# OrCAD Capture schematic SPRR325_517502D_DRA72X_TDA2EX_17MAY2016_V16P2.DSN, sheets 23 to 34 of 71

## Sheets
23 SH27 - DDR TERMNATION BANK 1: size B; rev: C
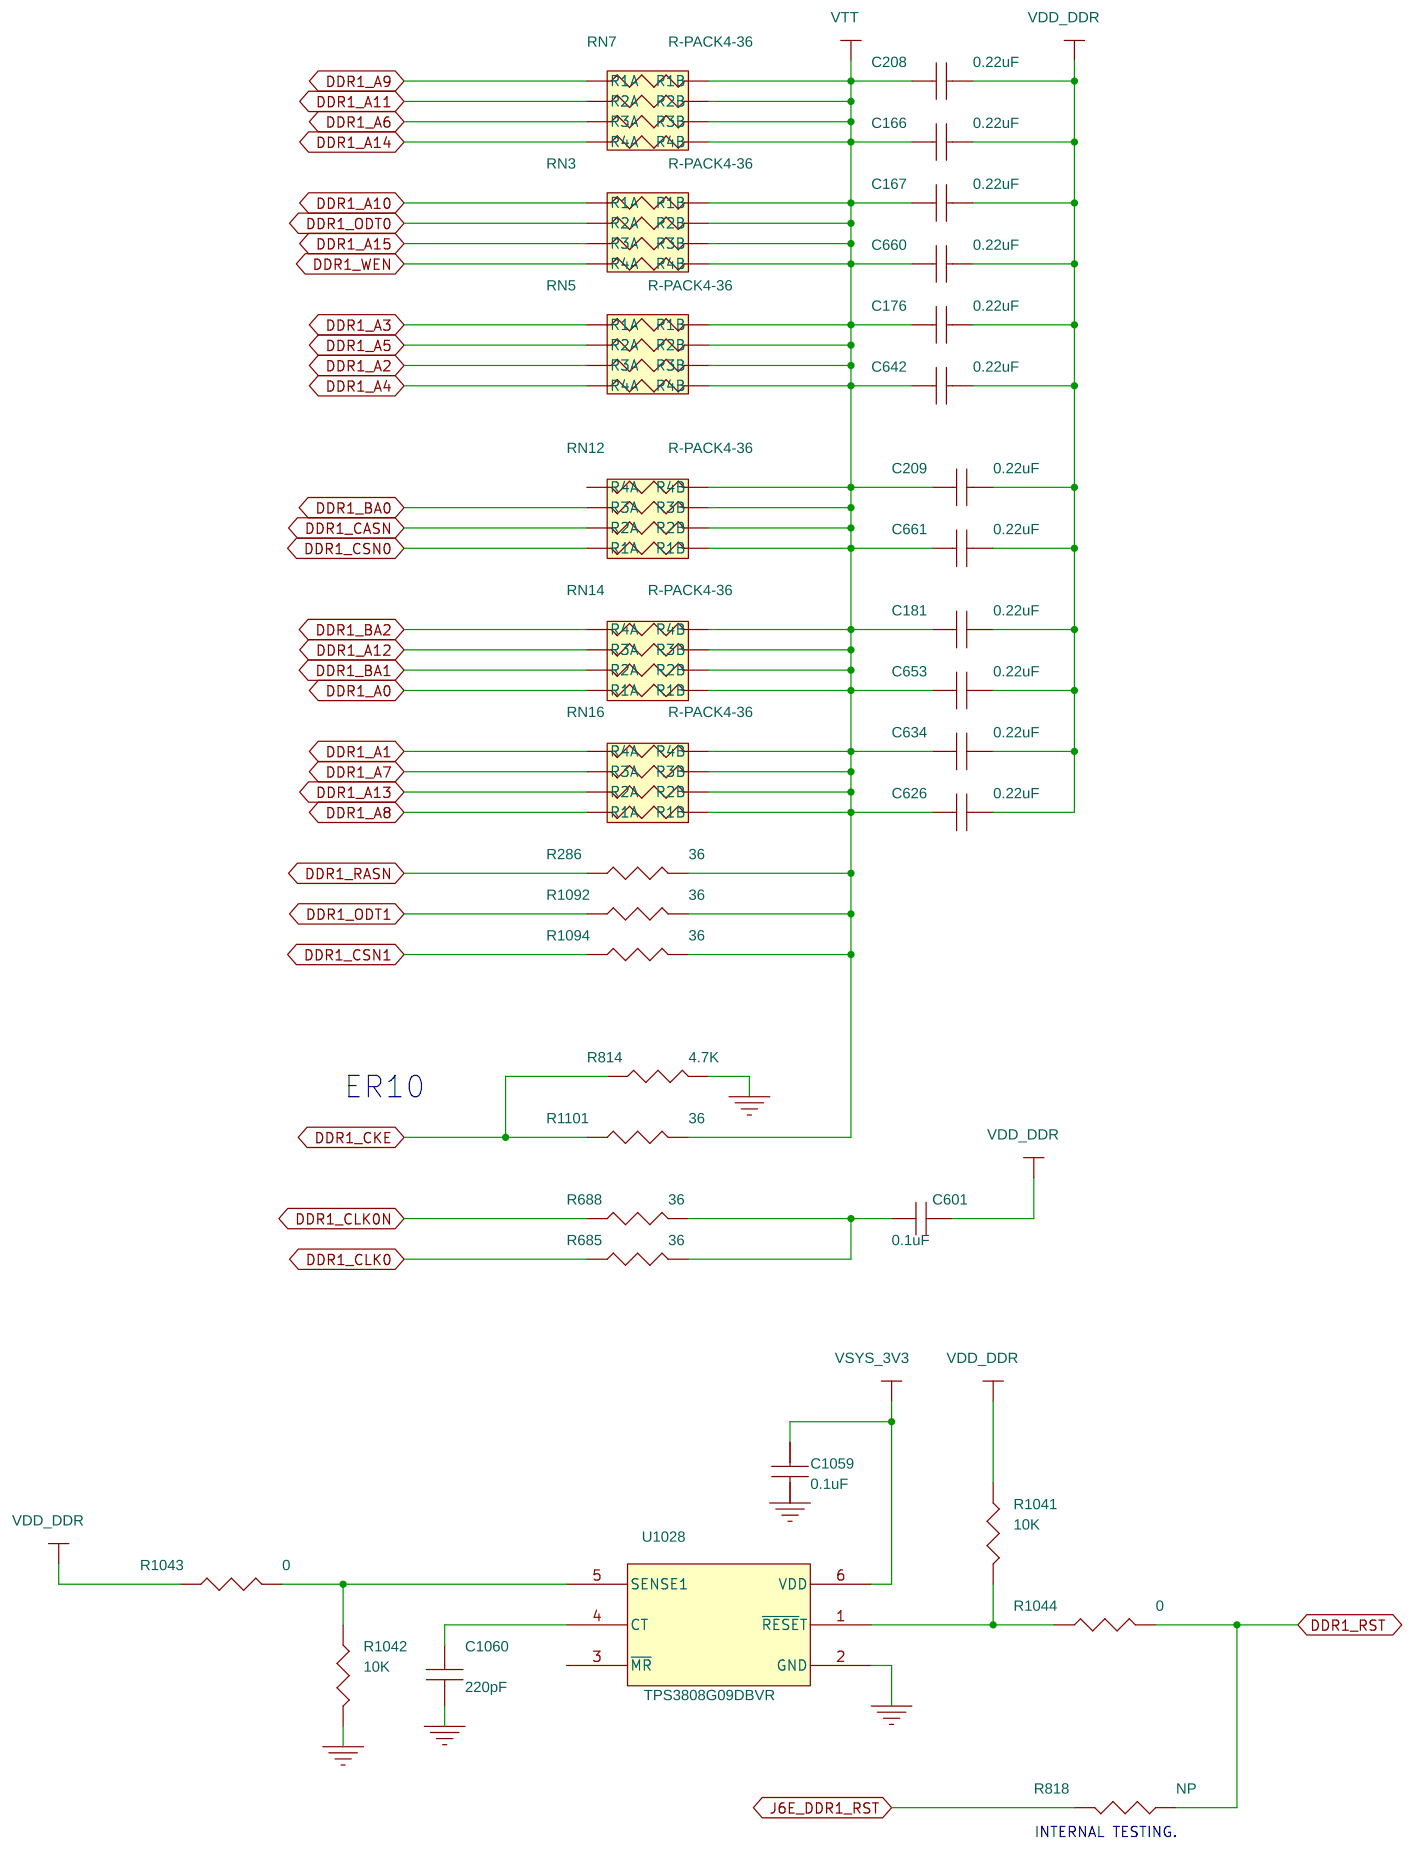
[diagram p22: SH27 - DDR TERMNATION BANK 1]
24 SH31 - MUX D GMPCA: size B; rev: A
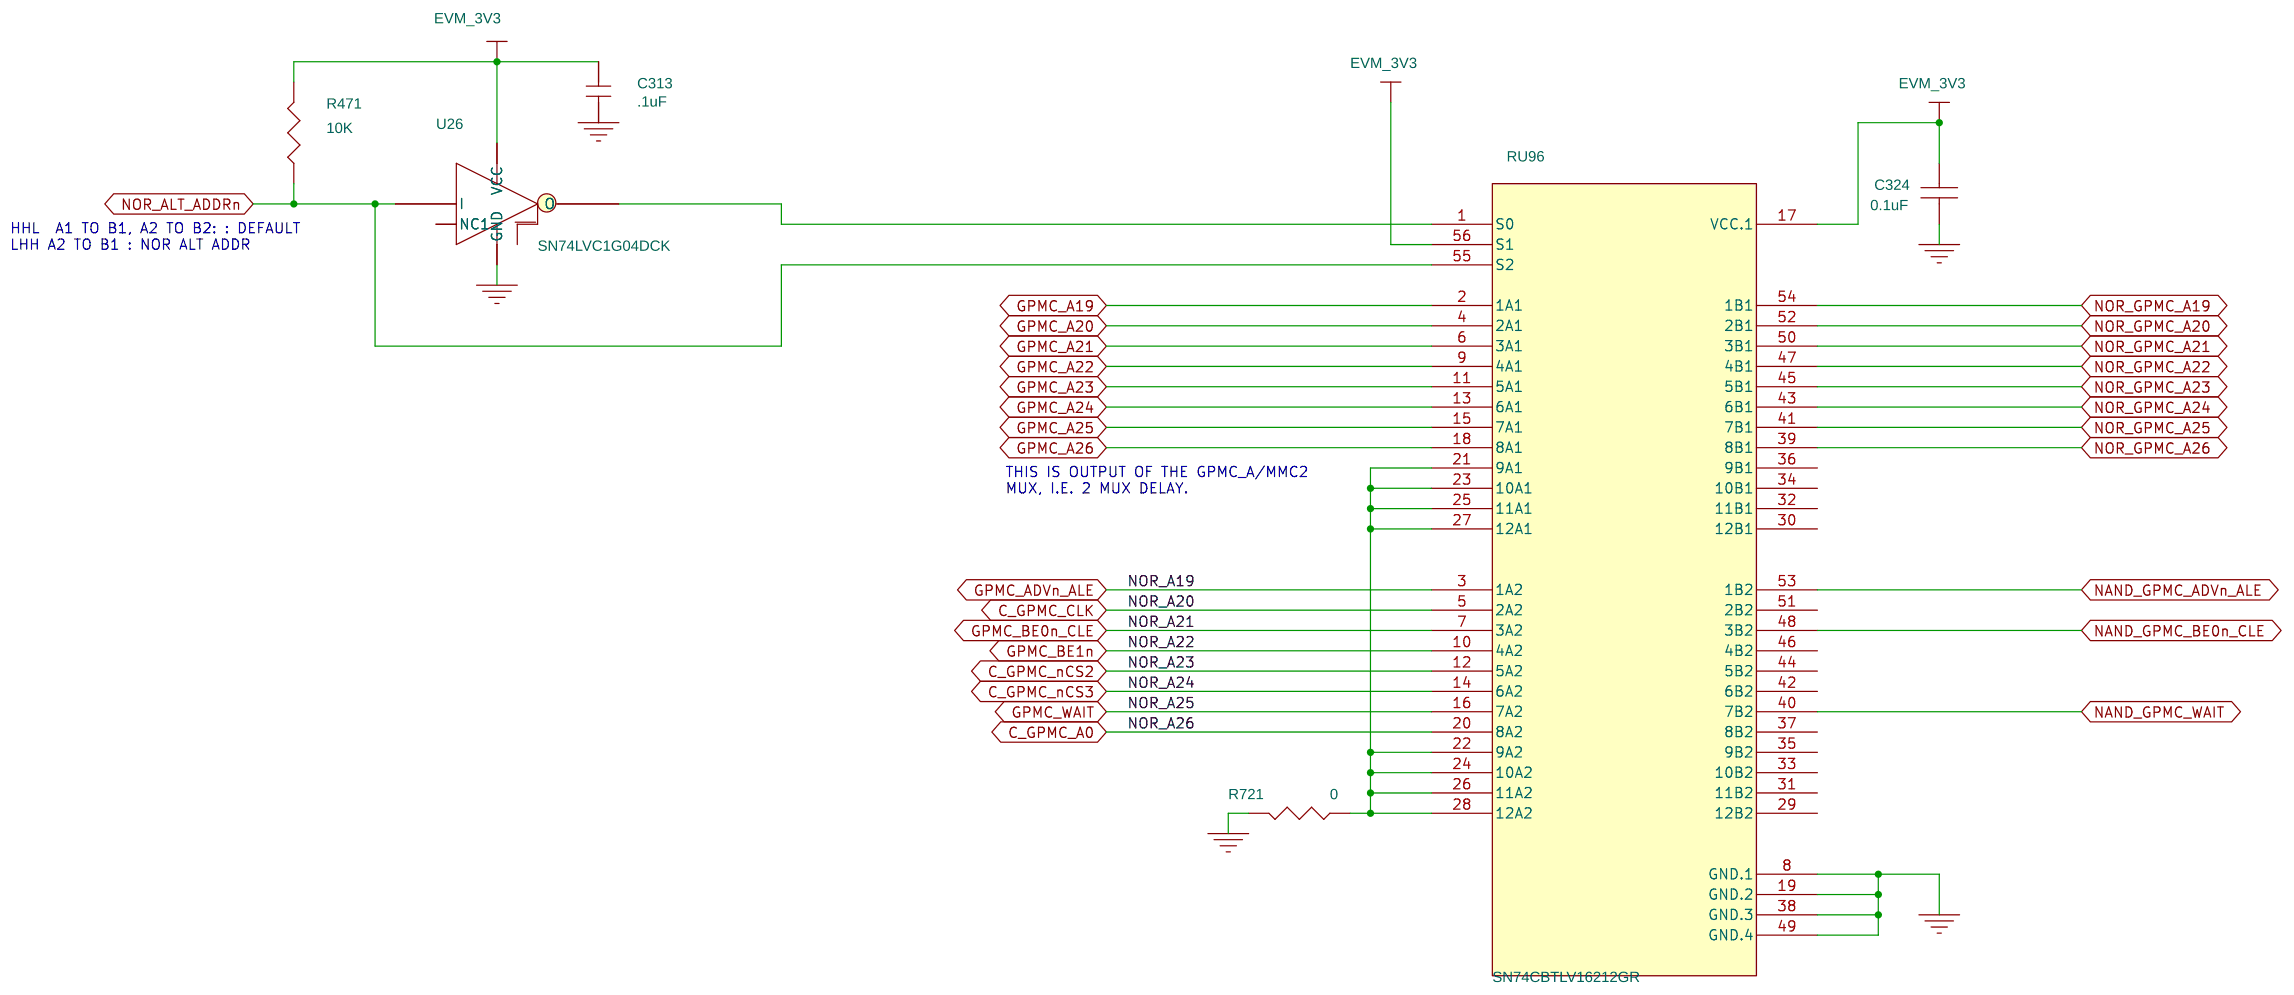
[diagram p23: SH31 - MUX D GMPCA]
25 SH32 - MUX E VIN2: size B
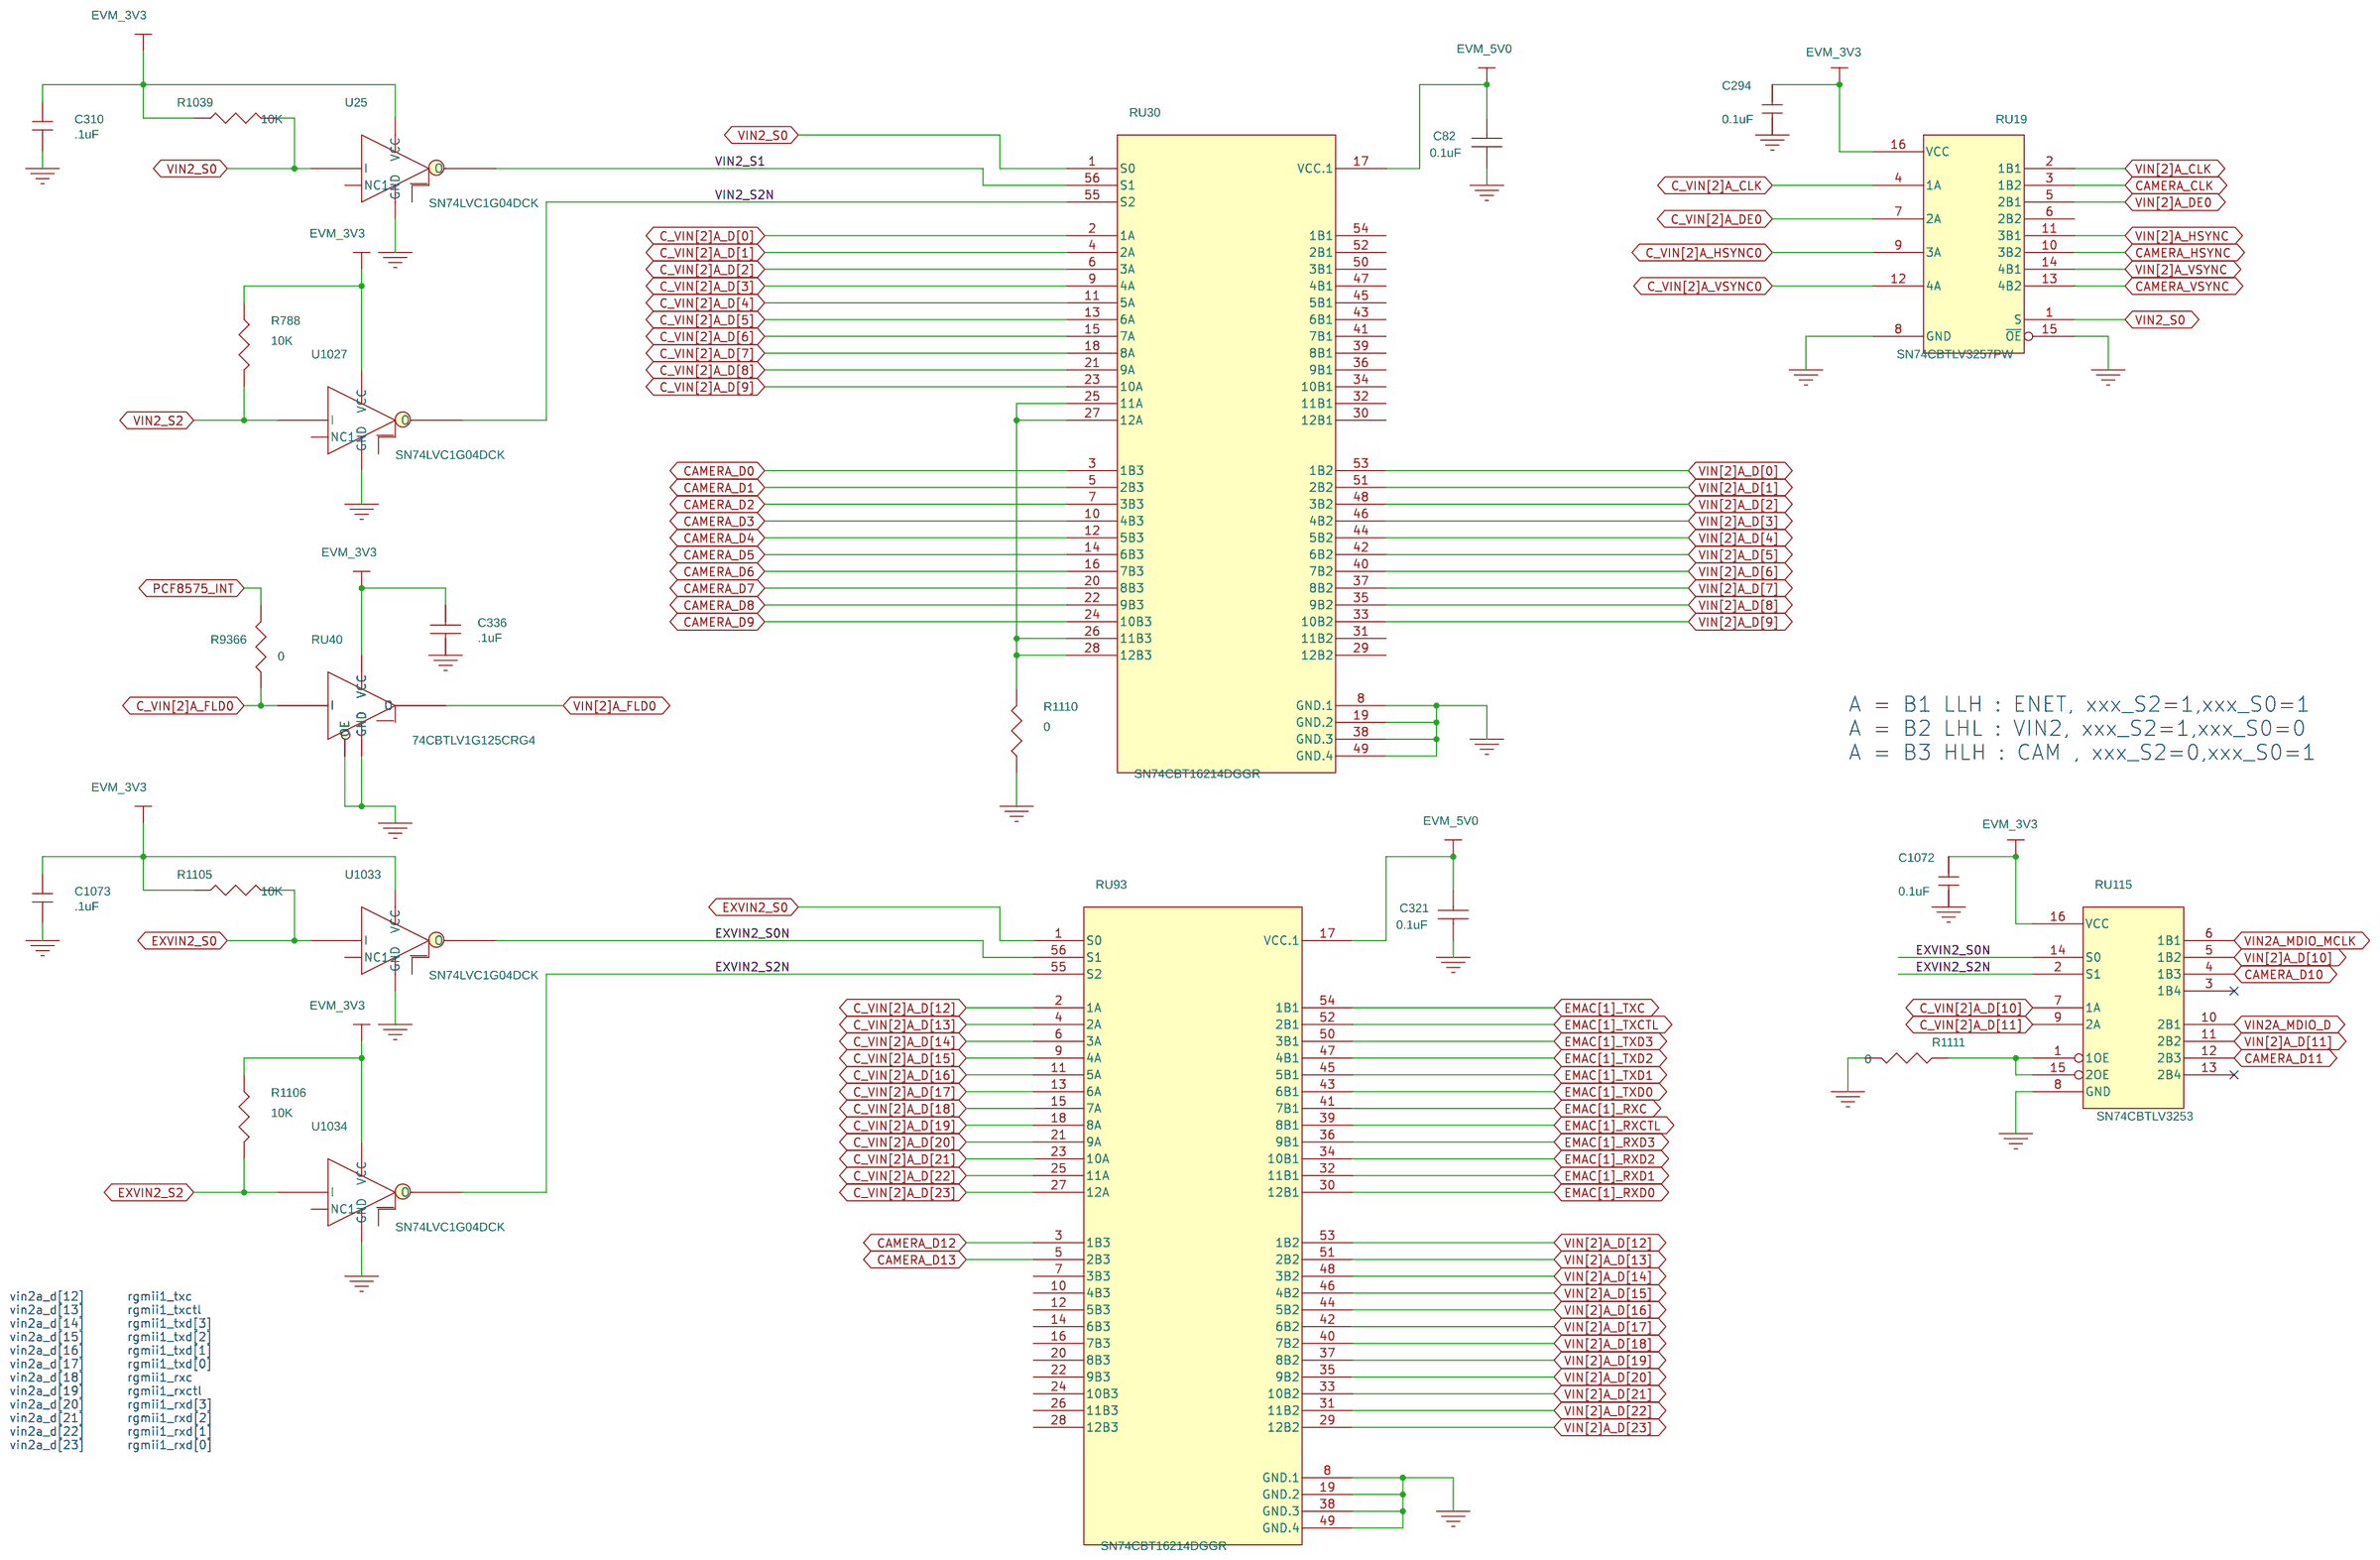
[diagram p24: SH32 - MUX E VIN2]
26 SH36 - MEM SPI FLASH: size B; rev: A
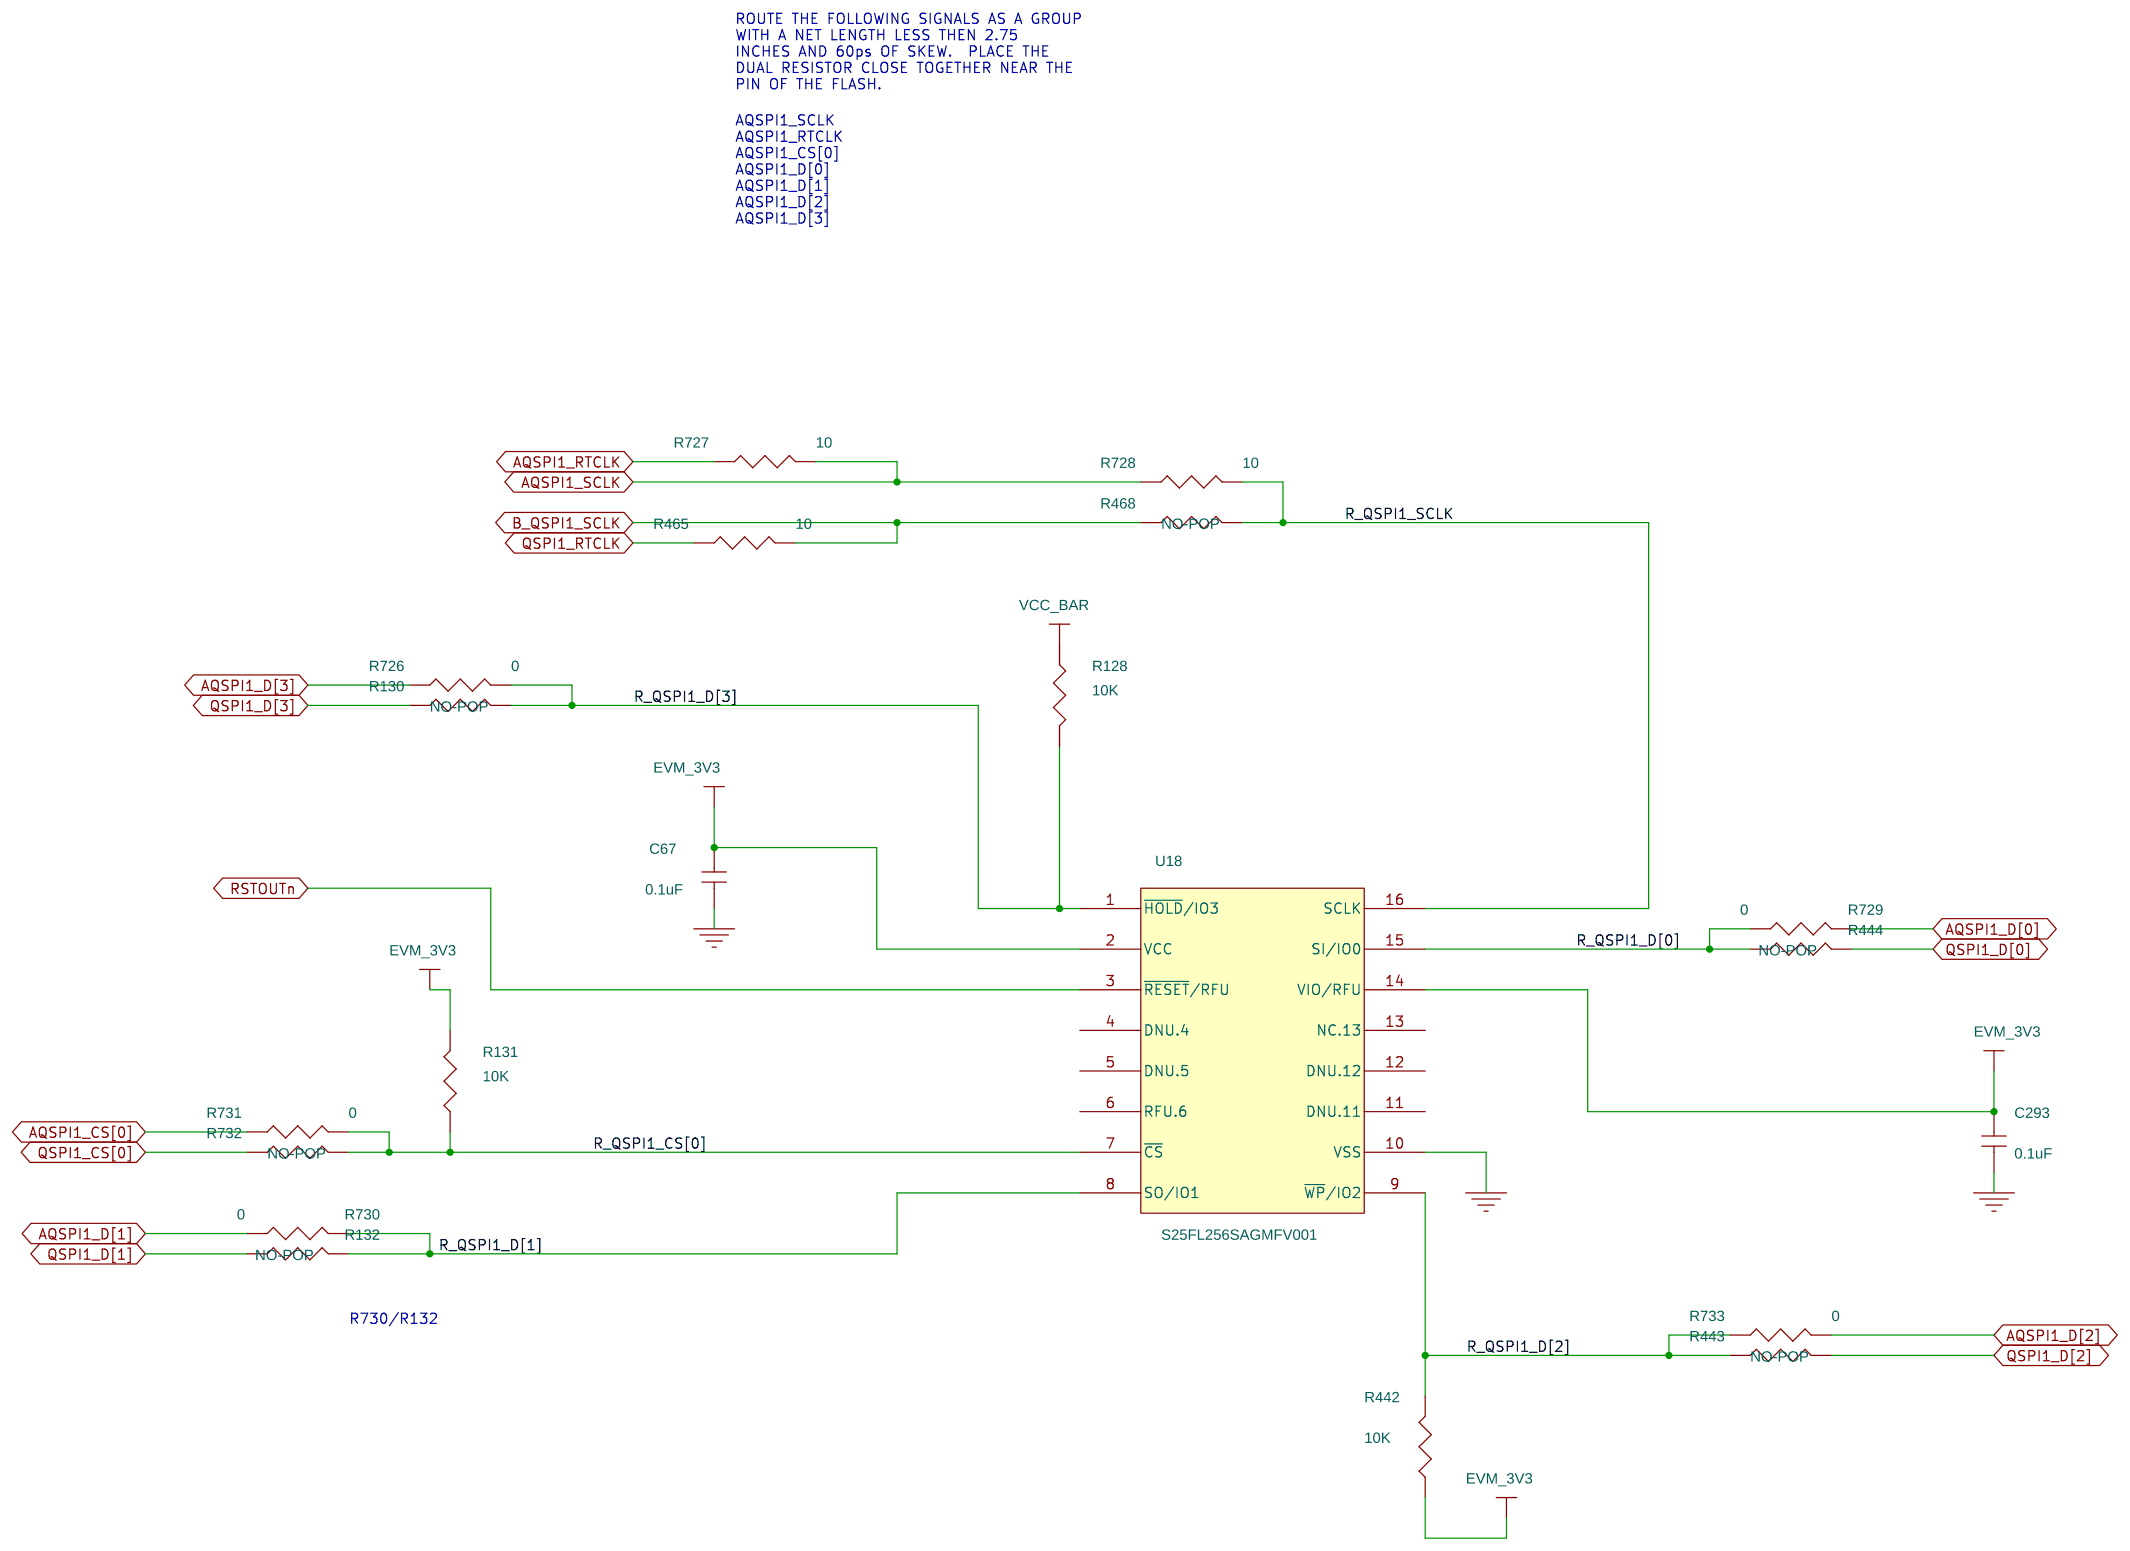
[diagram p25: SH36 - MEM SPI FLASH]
27 SH37 - MEM NAND FLASH: size B; rev: A
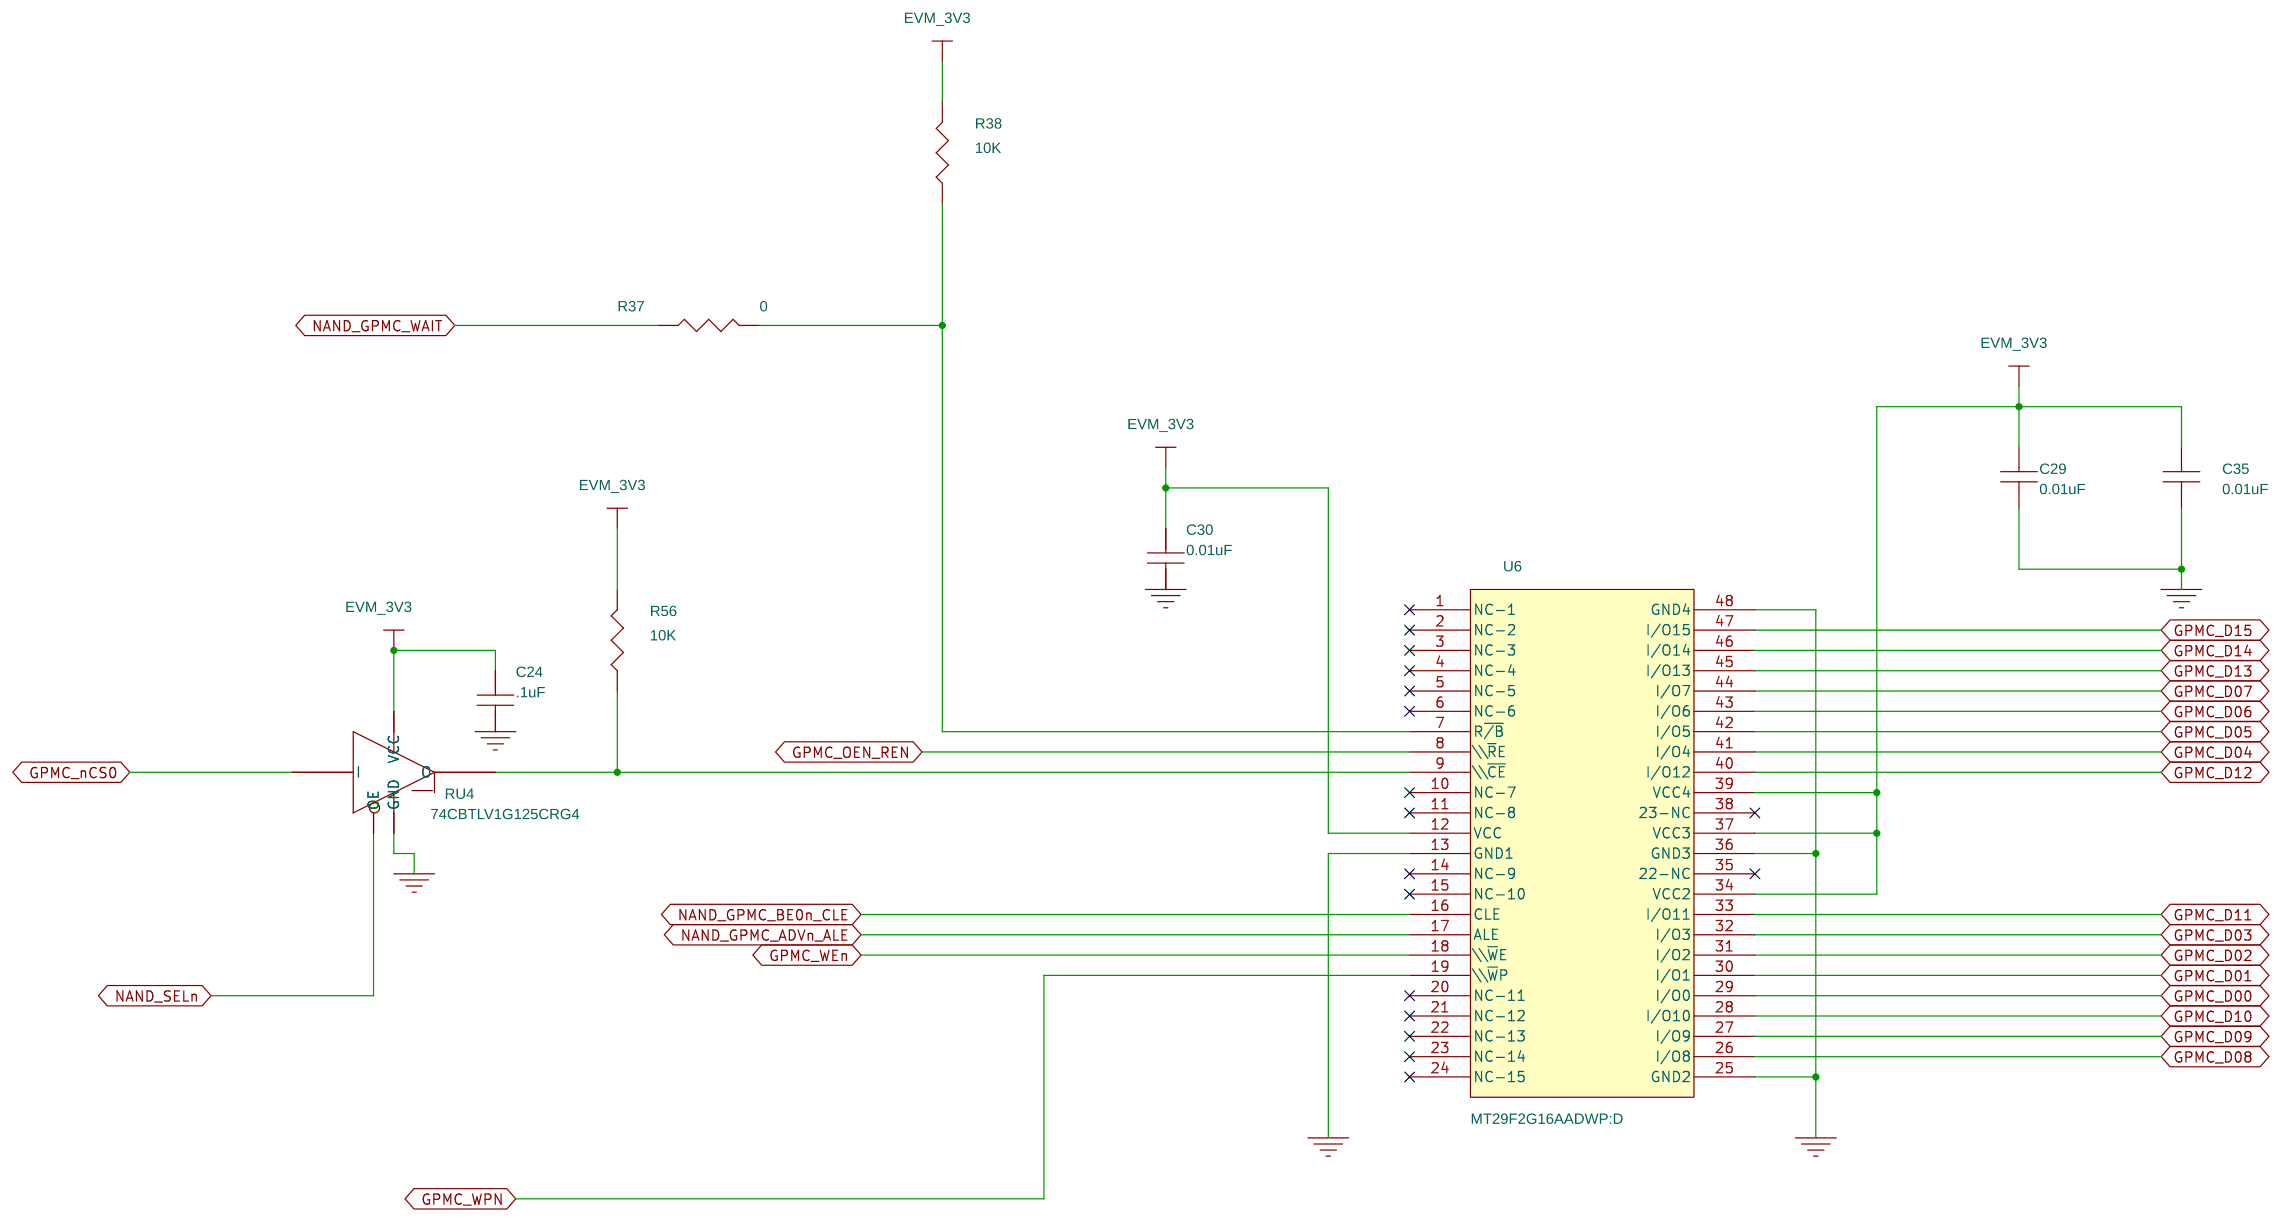
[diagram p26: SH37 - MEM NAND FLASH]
28 SH38 - MEM NOR FLASH: size B; rev: A
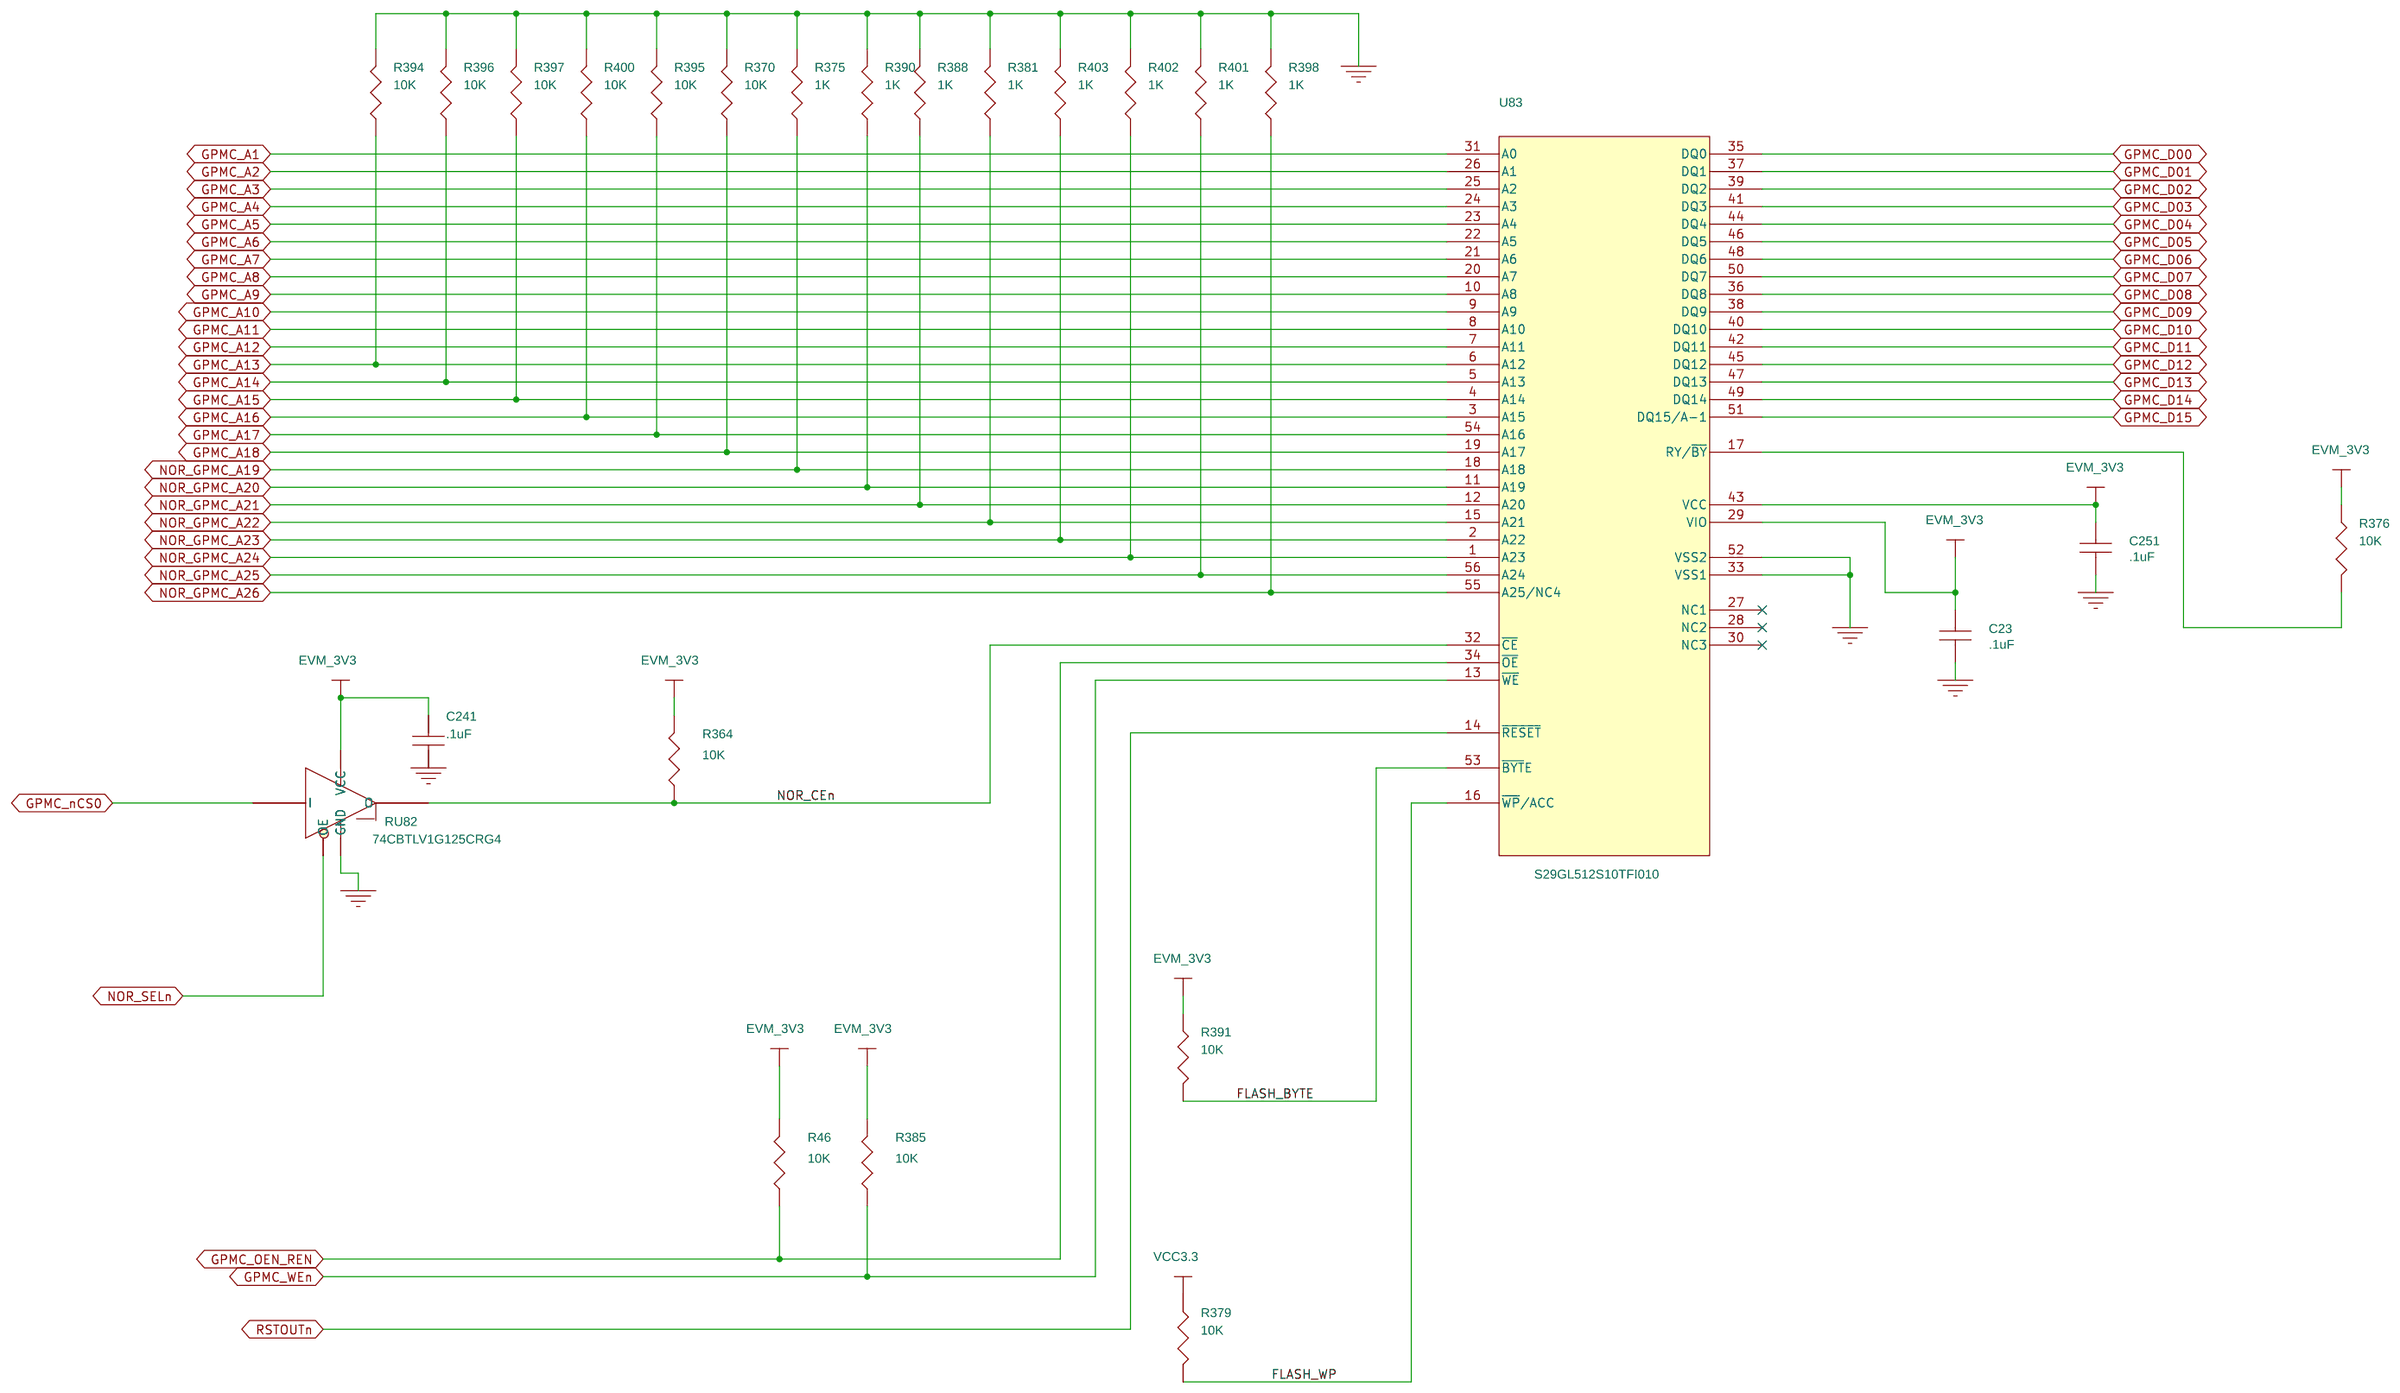
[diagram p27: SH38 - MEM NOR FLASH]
29 SH39 - MEM eMMC: size B; rev: C
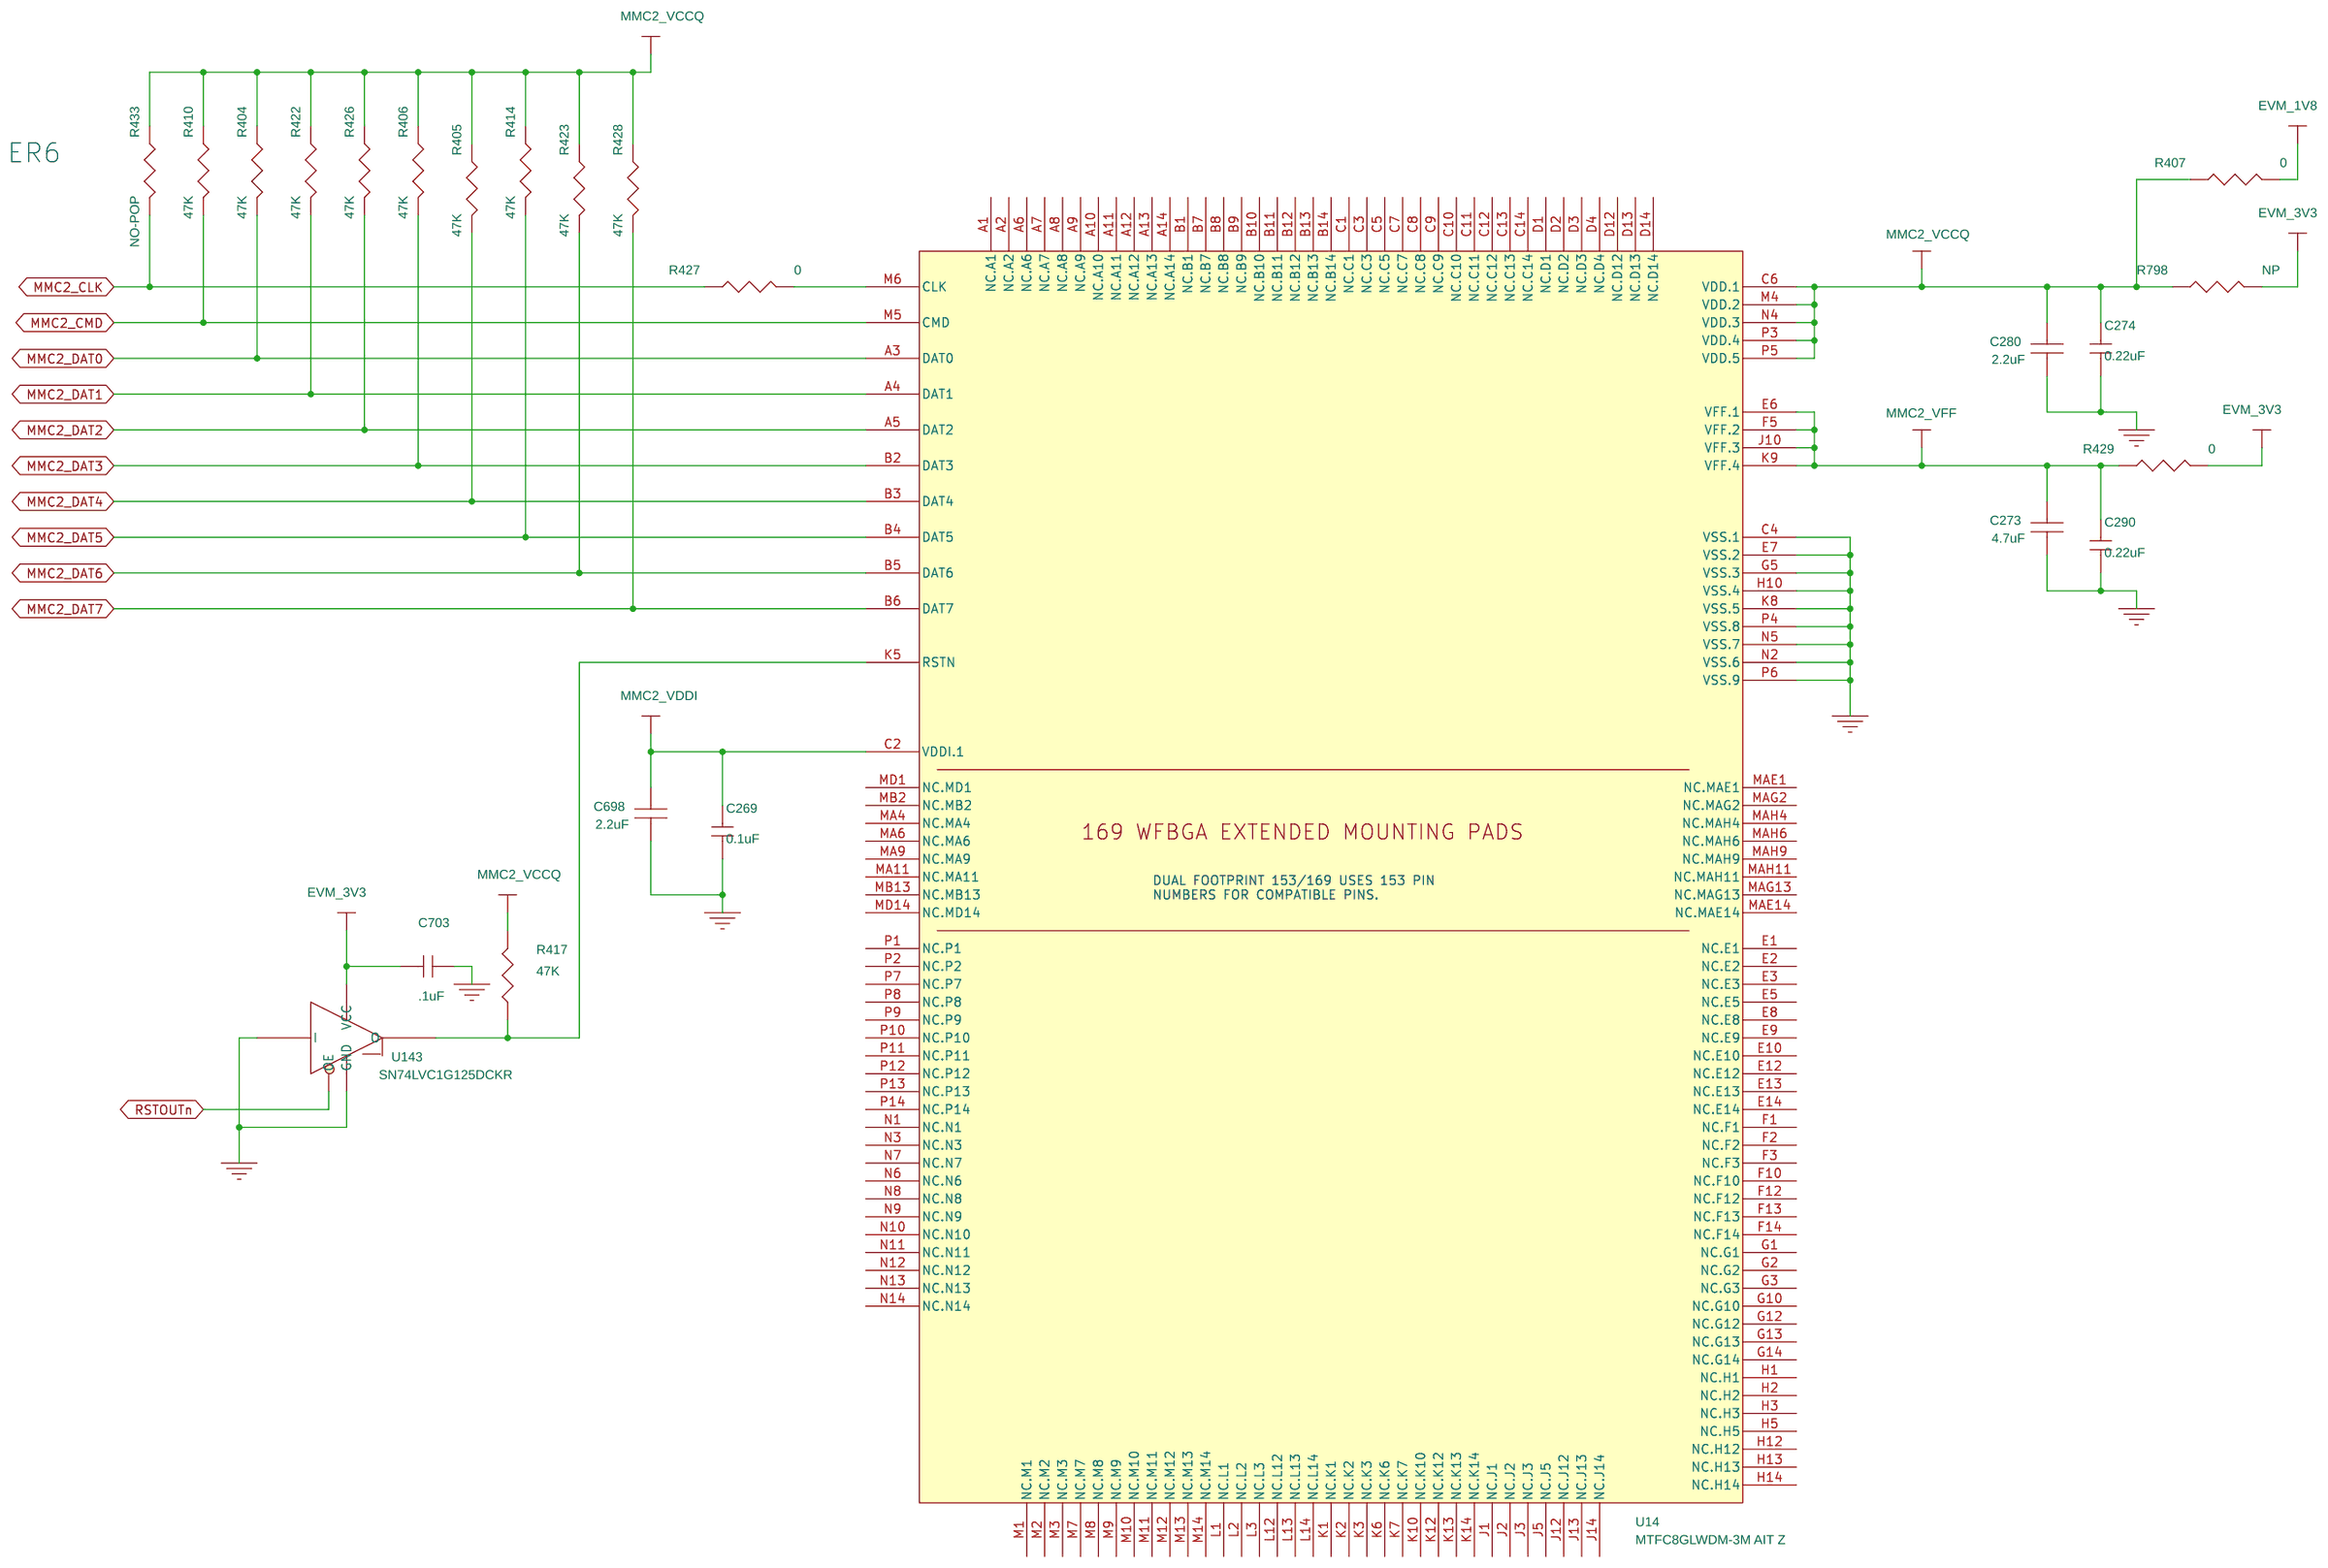
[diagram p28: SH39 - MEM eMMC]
30 SH40 - MEM SD CARD: size B; rev: C
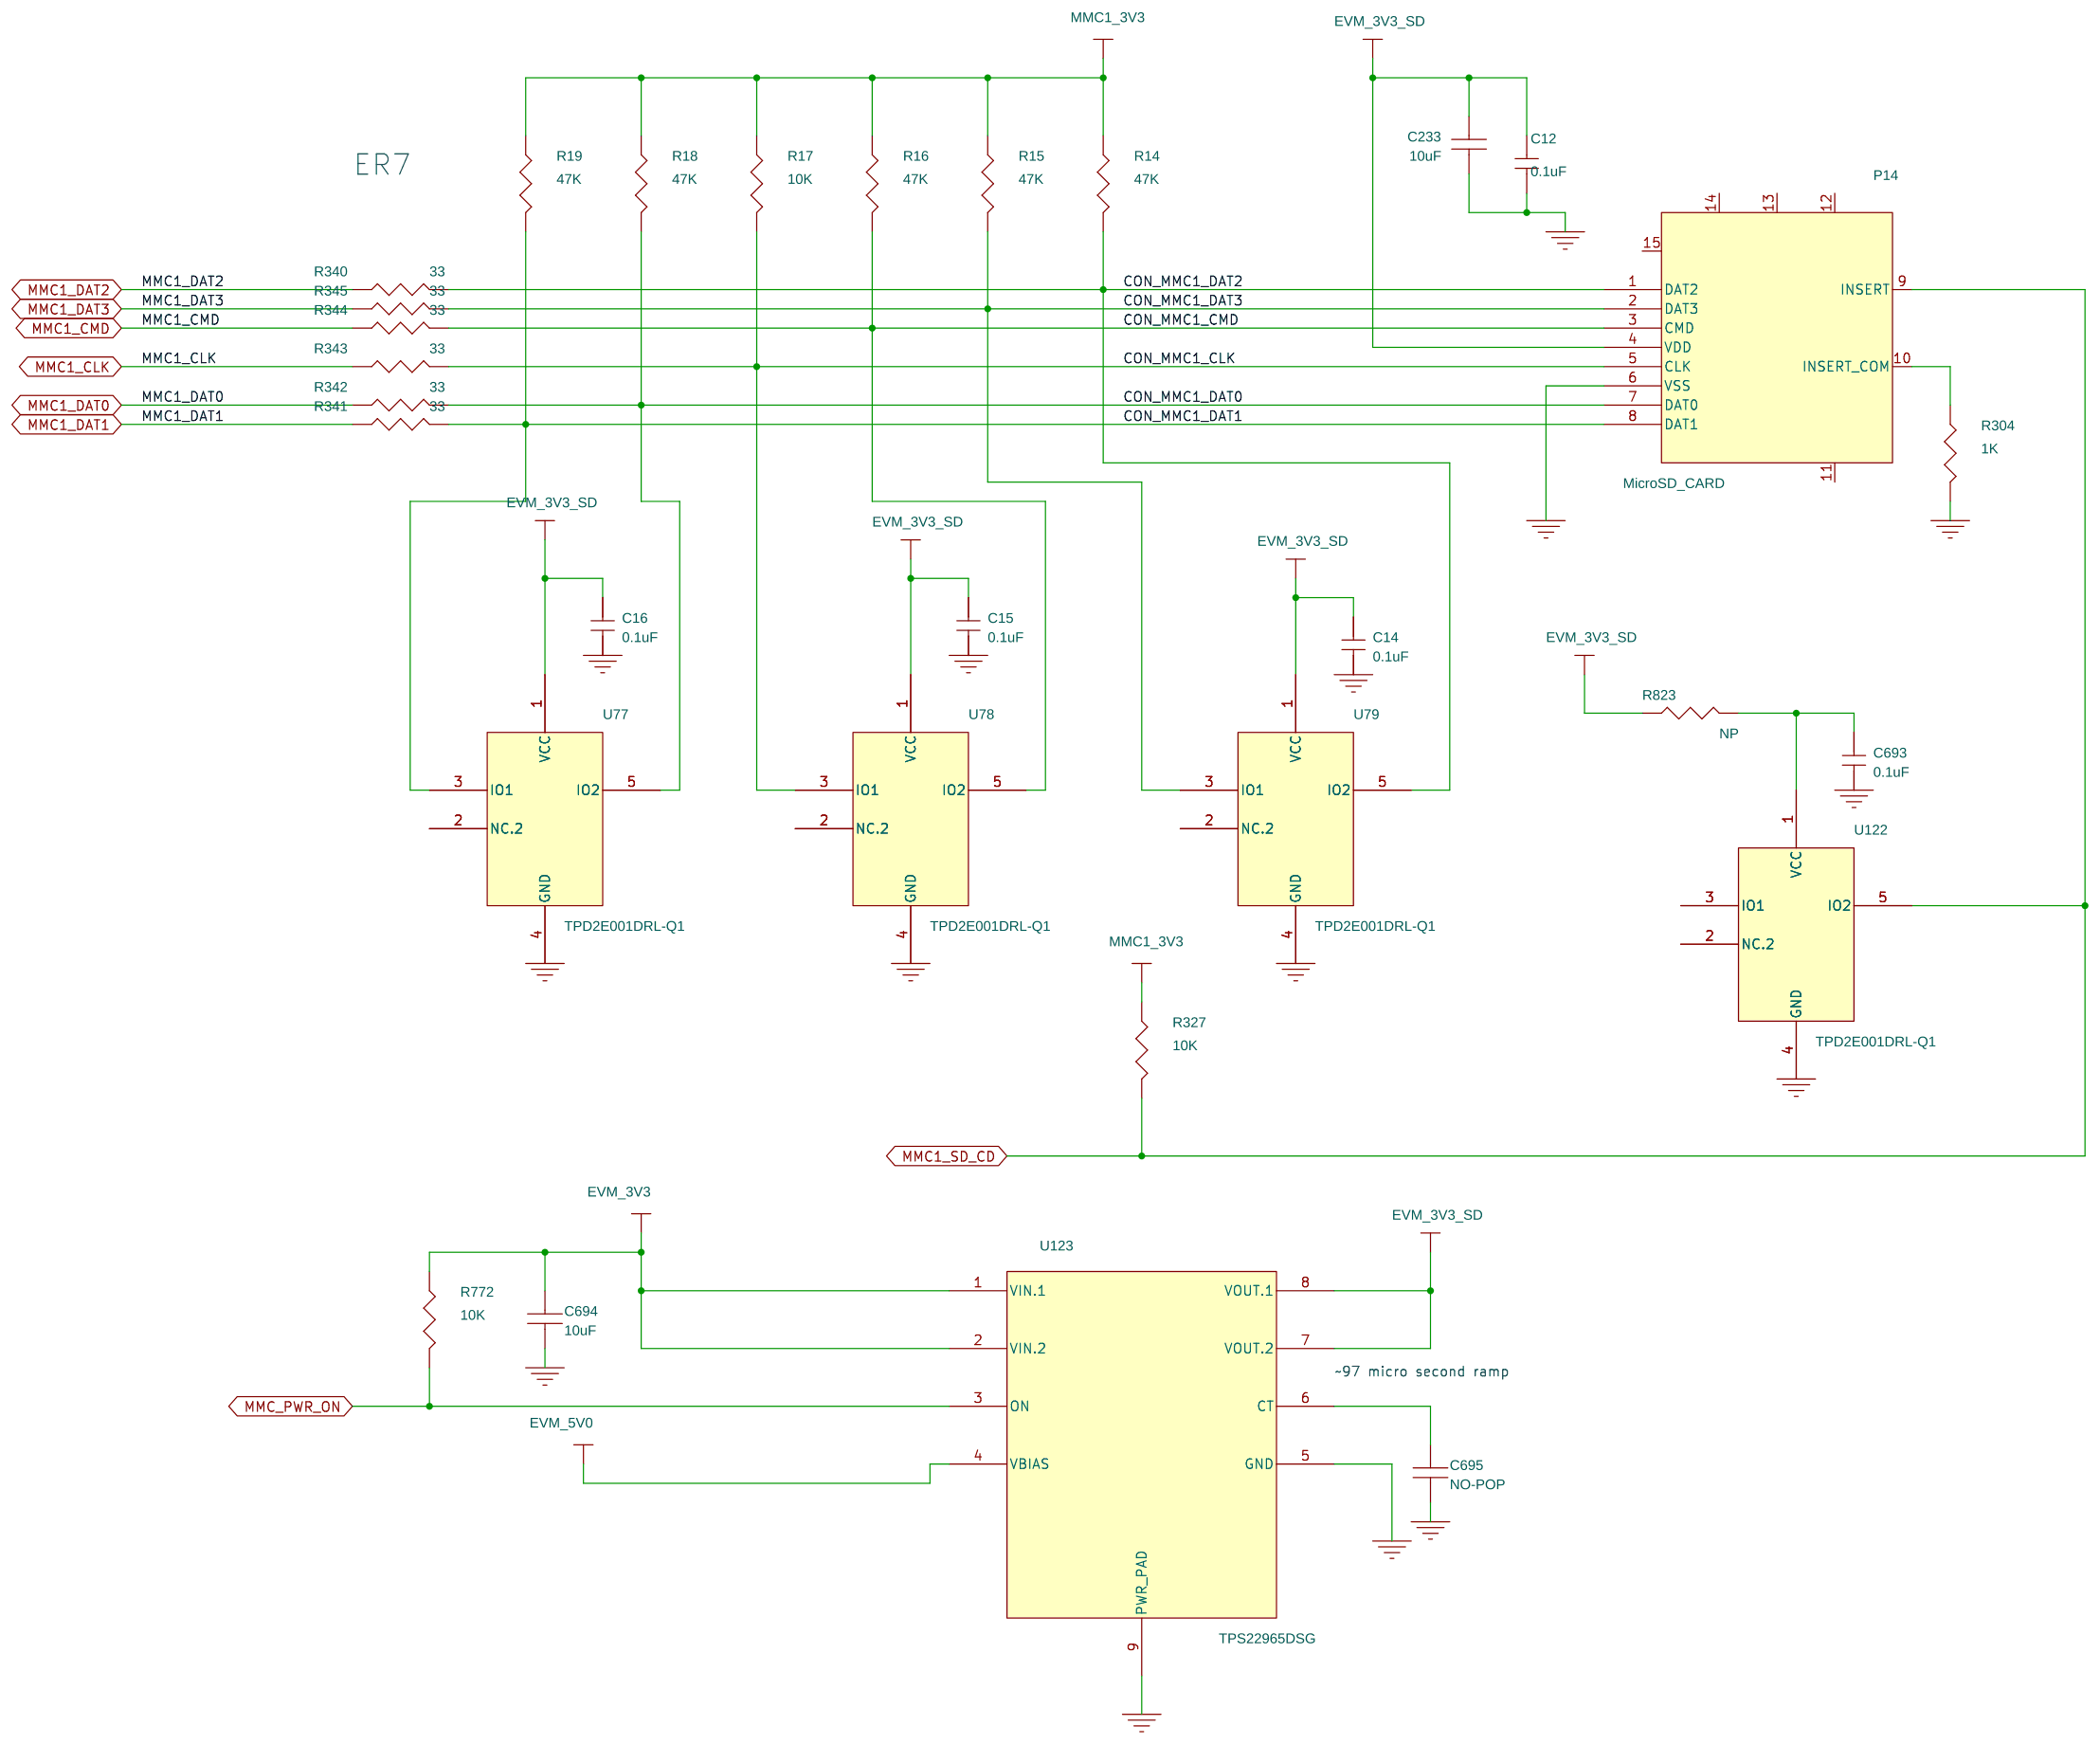
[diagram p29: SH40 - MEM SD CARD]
31 SH41 - USB VBUS: size B; rev: A
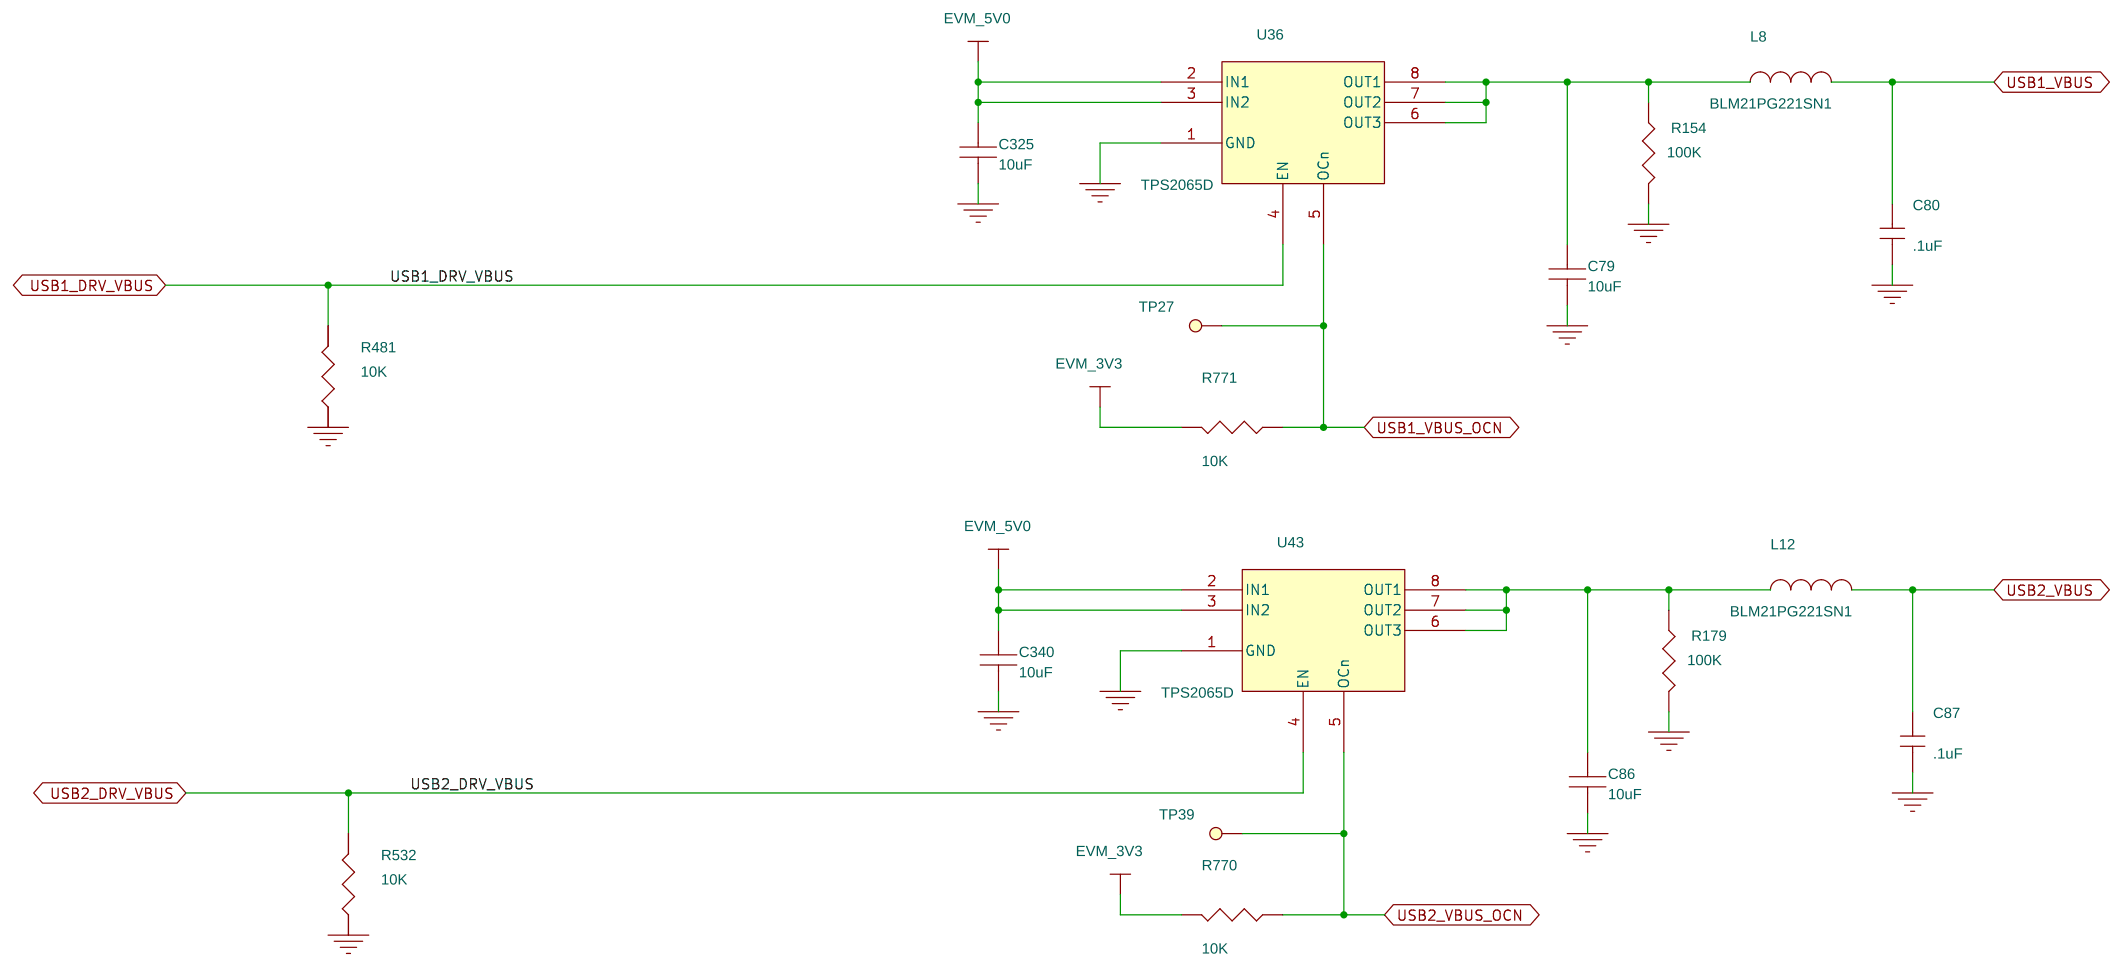
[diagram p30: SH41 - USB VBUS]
32 SH42 - USB CONNECTORS: size B; rev: B
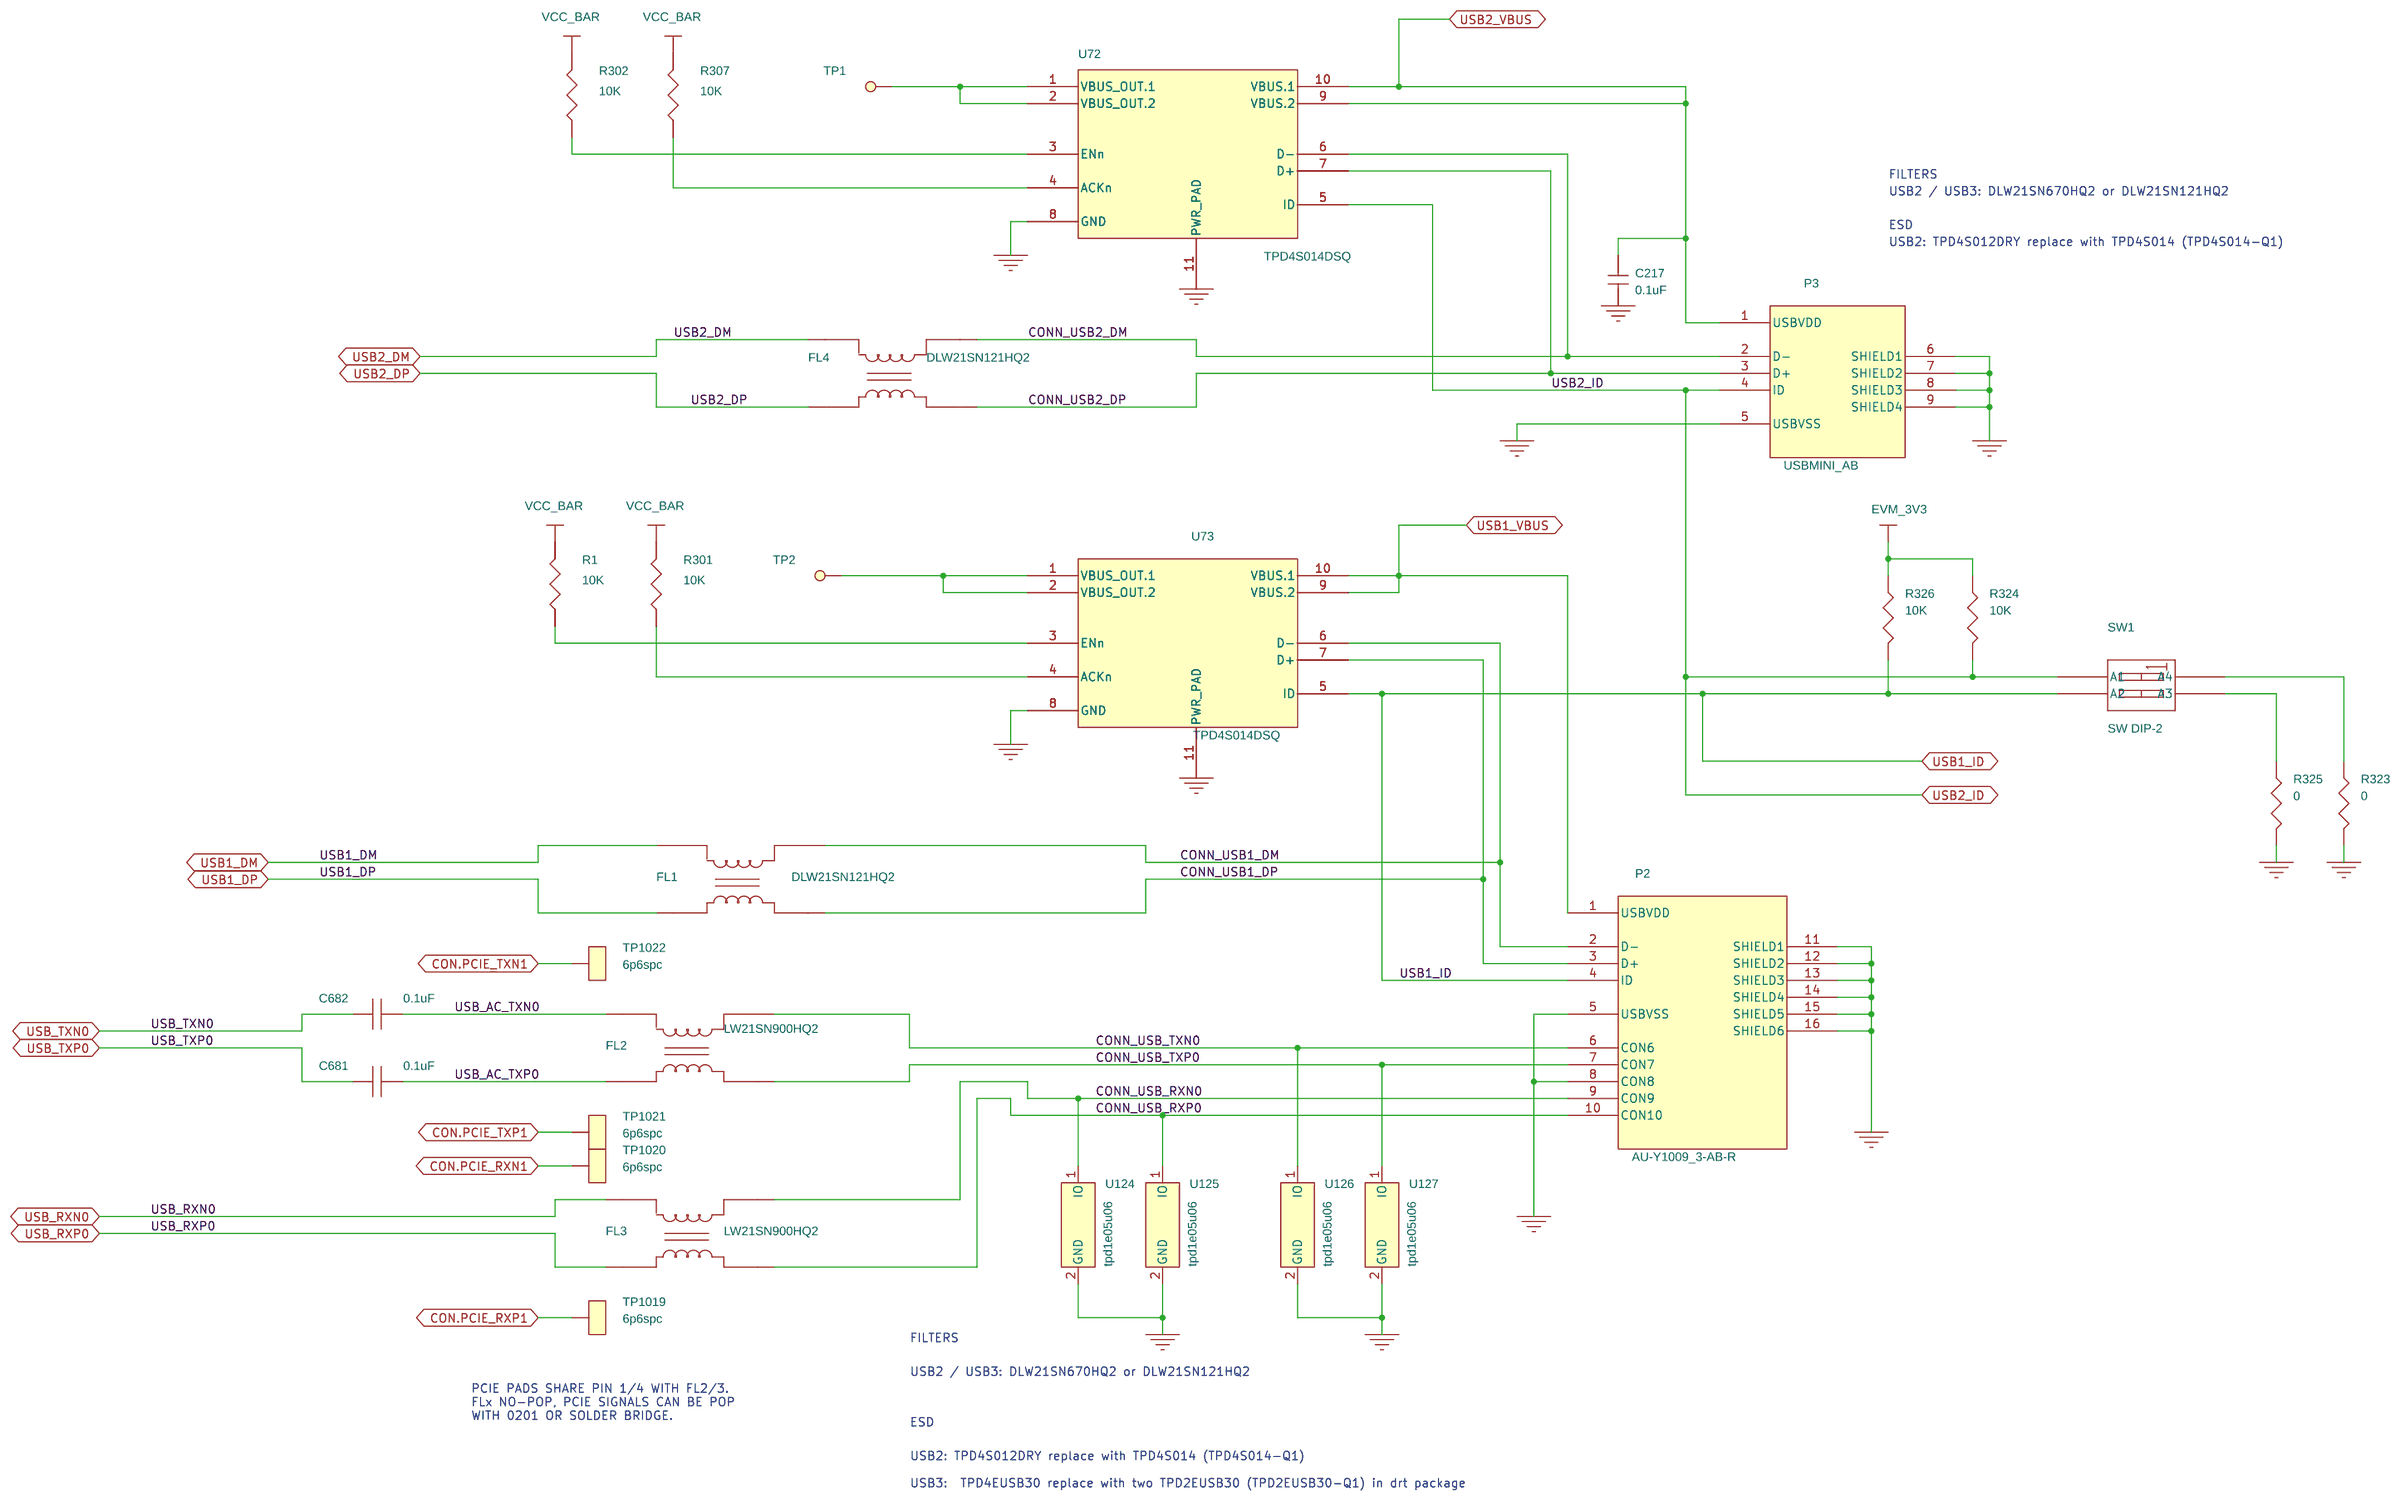
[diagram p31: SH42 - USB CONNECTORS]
33 SH43 - USB FTDI UART: size B; rev: A
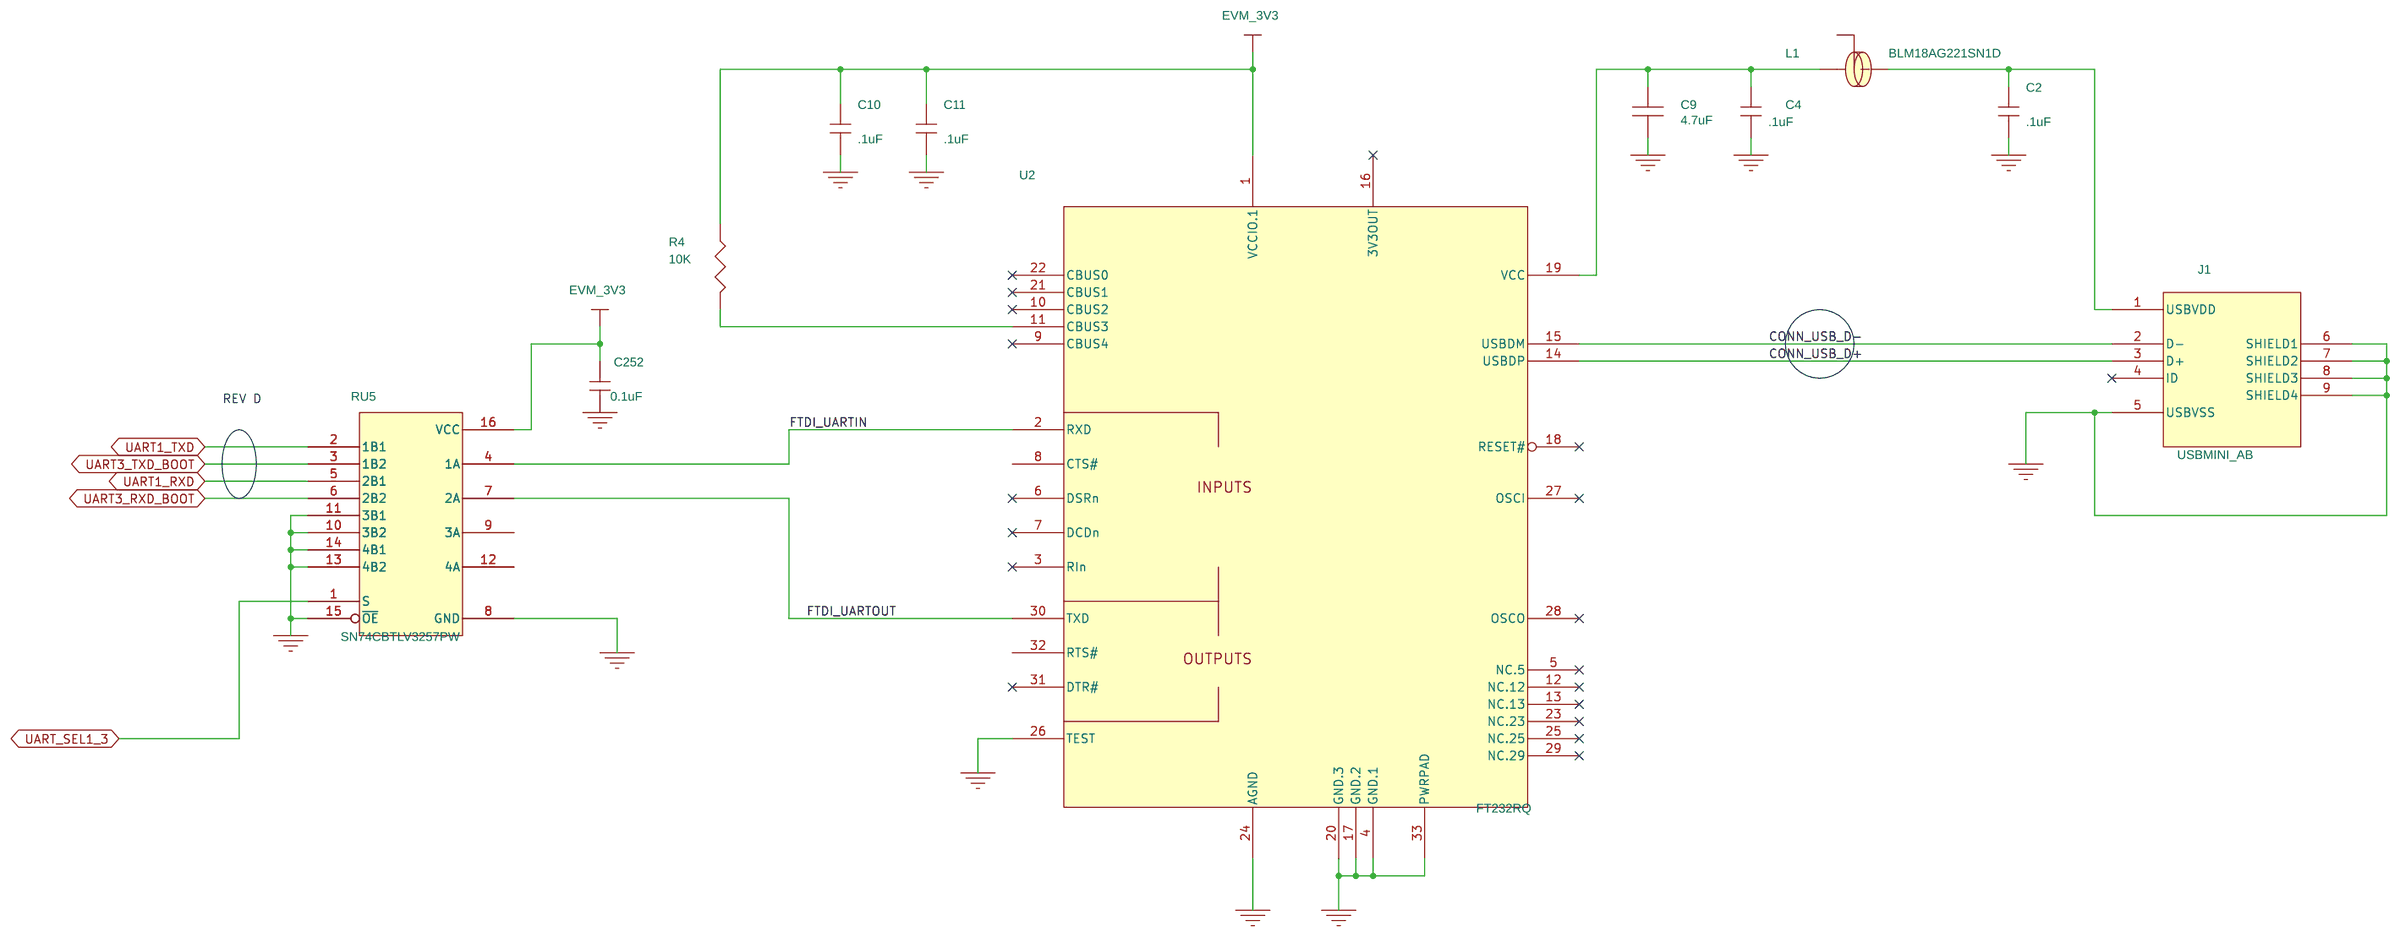
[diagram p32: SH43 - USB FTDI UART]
34 SH44 - AIC3106: size B; rev: A
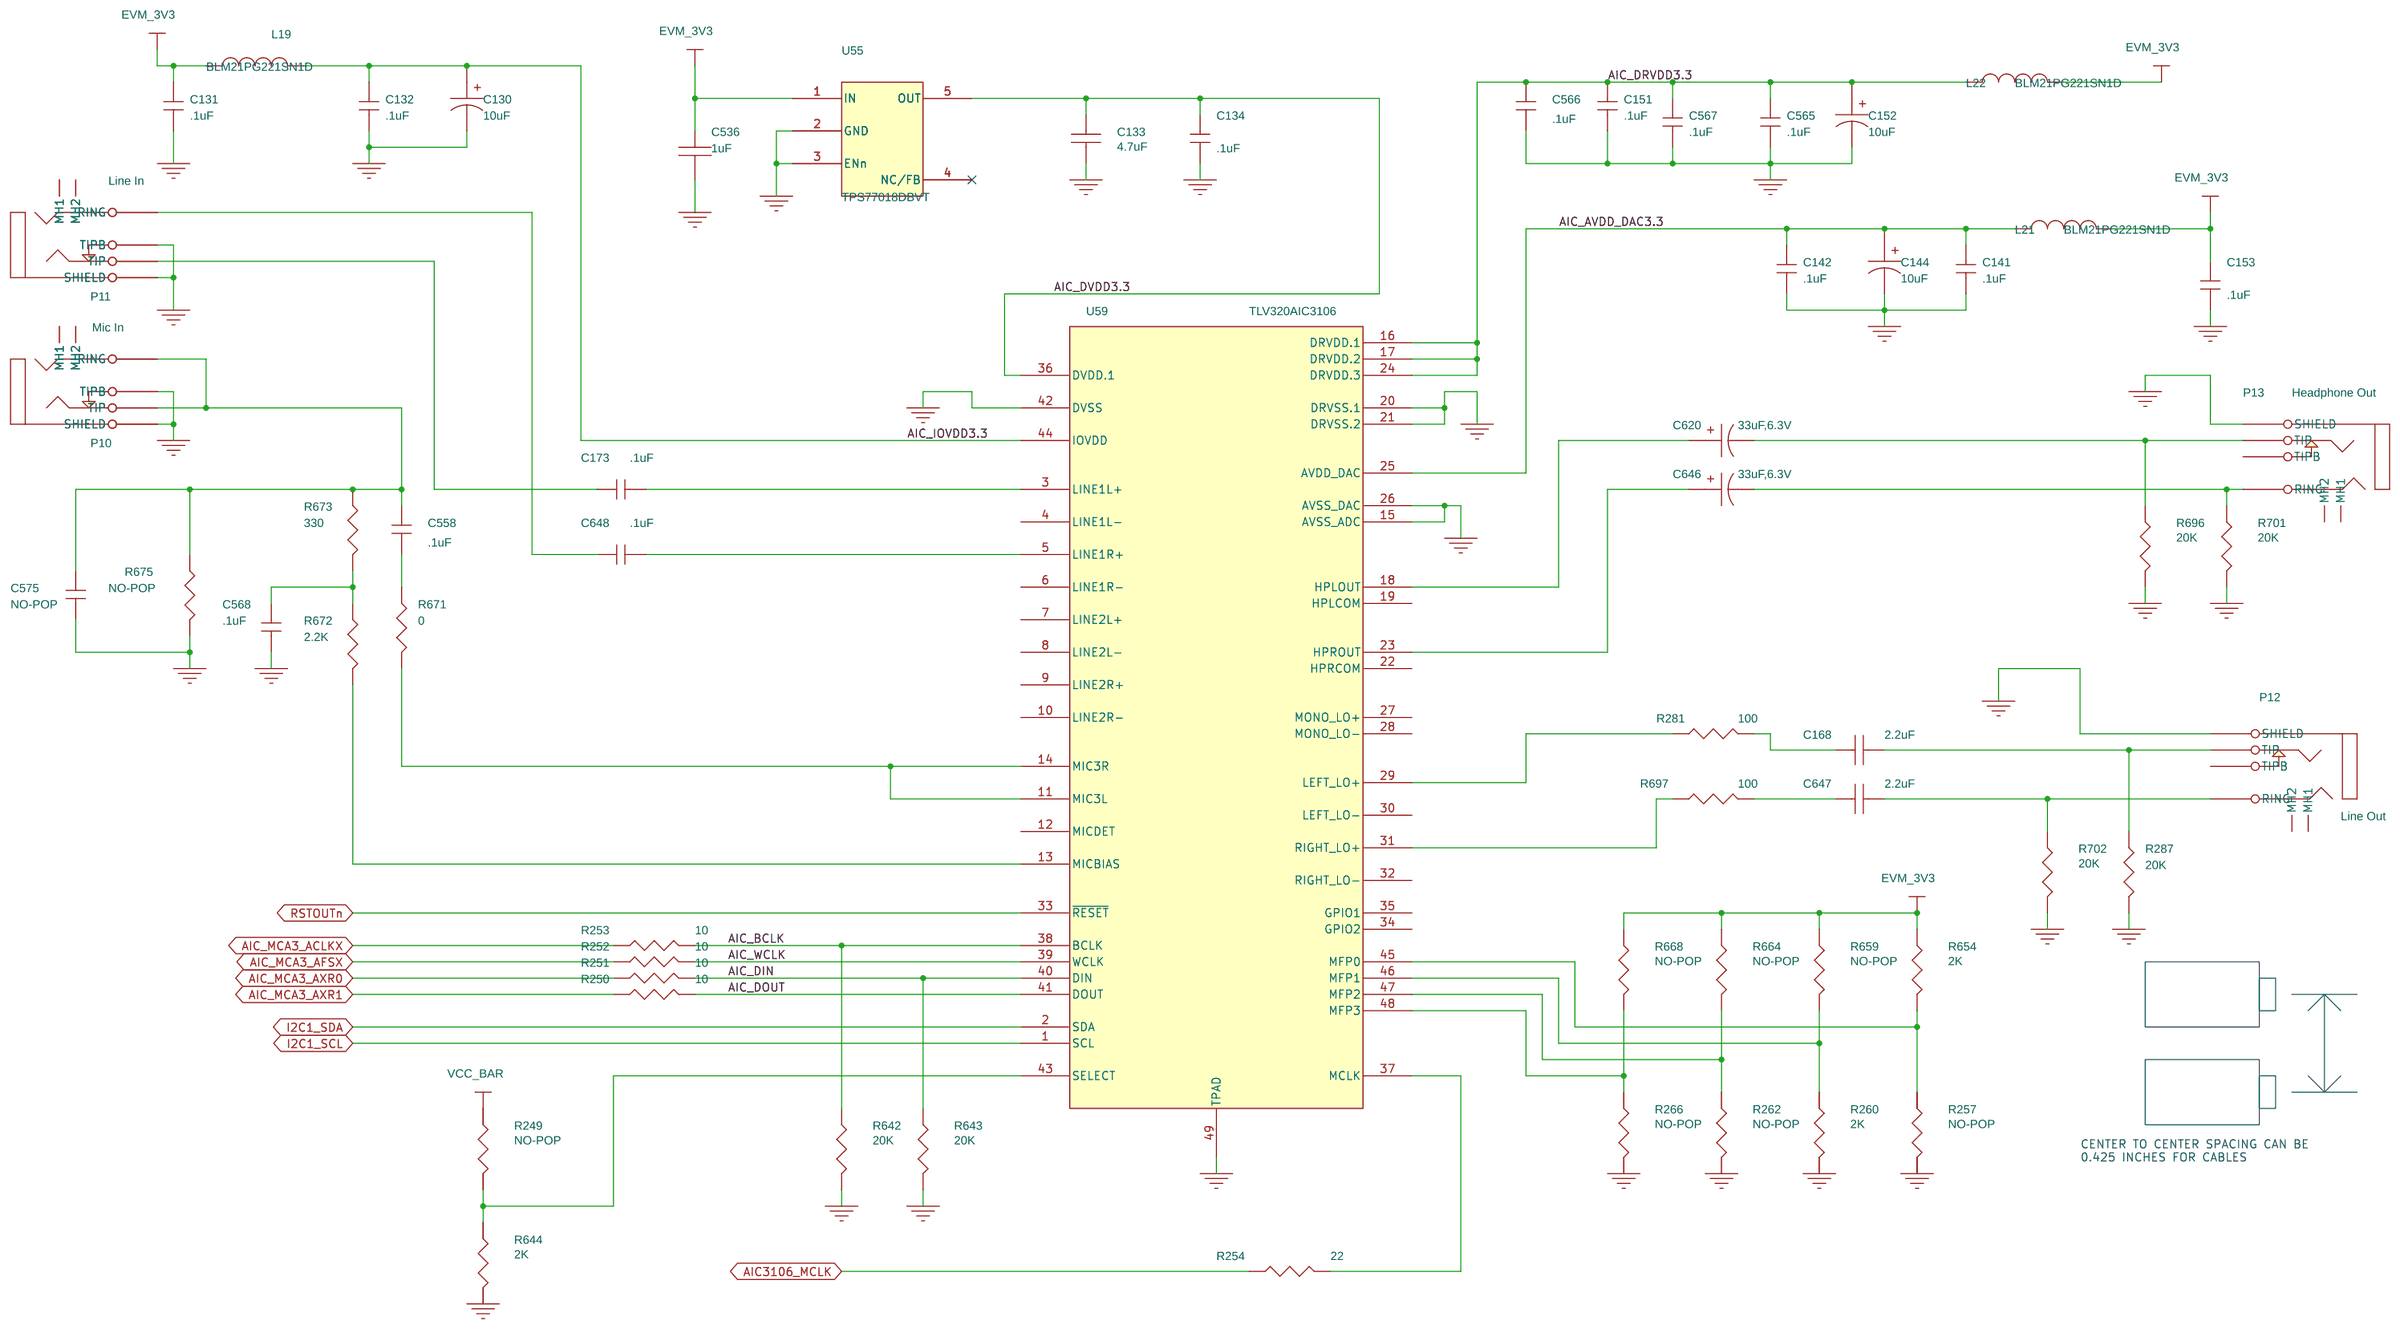
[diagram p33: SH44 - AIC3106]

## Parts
sheet SH27 - DDR TERMNATION BANK 1
C166  0.22uF  [c402-25]
C167  0.22uF  [c402-25]
C176  0.22uF  [c402-25]
C181  0.22uF  [c402-25]
C208  0.22uF  [c402-25]
C209  0.22uF  [c402-25]
C601  0.1uF  [c402-25]
C626  0.22uF  [c402-25]
C634  0.22uF  [c402-25]
C642  0.22uF  [c402-25]
C653  0.22uF  [c402-25]
C660  0.22uF  [c402-25]
C661  0.22uF  [c402-25]
C1059  0.1uF  [c402-25]
C1060  220pF  [c402-25]
R286  36  [r402-25]
R685  36  [r402-25]
R688  36  [r402-25]
R814  4.7K  [r402-25]
R818  NP  [r402-25]
R1041  10K  [r402-25]
R1042  10K  [r402-25]
R1043  0  [r402-25]
R1044  0  [r402-25]
R1092  36  [r402-25]
R1094  36  [r402-25]
R1101  36  [r402-25]
RN3  R-PACK4-36  [rpak8-10x25-28v]
RN5  R-PACK4-36  [rpak8-10x25-28v]
RN7  R-PACK4-36  [rpak8-10x25-28v]
RN12  R-PACK4-36  [rpak8-10x25-28v]
RN14  R-PACK4-36  [rpak8-10x25-28v]
RN16  R-PACK4-36  [rpak8-10x25-28v]
U1028  TPS3808G09DBVR  [DBV6-27X39-6]
sheet SH31 - MUX D GMPCA
C313  .1uF  [c402-25]
C324  0.1uF  [c402-25]
R471  10K  [r201-6p6spc]
R721  0  [r201-6p6spc]
RU96  SN74CBTLV16212GR  [dgg56-12x80]
U26  SN74LVC1G04DCK  [dck-5]
sheet SH32 - MUX E VIN2
C82  0.1uF  [c402-25]
C294  0.1uF  [c402-25]
C310  .1uF  [c402-25]
C321  0.1uF  [c402-25]
C336  .1uF  [c402-25]
C1072  0.1uF  [c402-25]
C1073  .1uF  [c402-25]
R788  10K  [r201-6p6spc]
R1039  10K  [r201-6p6spc]
R1105  10K  [r201-6p6spc]
R1106  10K  [r201-6p6spc]
R1110  0  [r201-6p6spc]
R1111  0  [r201-6p6spc]
R9366  0  [r201-6p6spc]
RU19  SN74CBTLV3257PW  [tssop16-14x70]
RU30  SN74CBT16214DGGR  [dgg56-12x80]
RU40  74CBTLV1G125CRG4  [dck-5]
RU93  SN74CBT16214DGGR  [dgg56-12x80]
RU115  SN74CBTLV3253  [tssop16-14x70]
U25  SN74LVC1G04DCK  [dck-5]
U1027  SN74LVC1G04DCK  [dck-5]
U1033  SN74LVC1G04DCK  [dck-5]
U1034  SN74LVC1G04DCK  [dck-5]
sheet SH36 - MEM SPI FLASH
C67  0.1uF  [c402-25]
C293  0.1uF  [c402-25]
R128  10K  [r402-25]
R130  NO-POP  [r402-25]
R131  10K  [r402-25]
R132  NO-POP  [r402-25]
R442  10K  [r402-25]
R443  NO-POP  [r402-25]
R444  NO-POP  [r402-25]
R465  10  [r402-25]
R468  NO-POP  [r402-25]
R726  0  [r402-25]
R727  10  [r402-25]
R728  10  [r402-25]
R729  0  [r402-25]
R730  0  [r402-25]
R731  0  [r402-25]
R732  NO-POP  [r402-25]
R733  0  [r402-25]
U18  S25FL256SAGMFV001  [so16-25x75-300]
sheet SH37 - MEM NAND FLASH
C24  .1uF  [c402-25]
C29  0.01uF  [c402-25]
C30  0.01uF  [c402-25]
C35  0.01uF  [c402-25]
R37  0  [r402-25]
R38  10K  [r402-25]
R56  10K  [r402-25]
RU4  74CBTLV1G125CRG4  [dck-5]
U6  MT29F2G16AADWP:D  [tsop48-10x60-micron]
sheet SH38 - MEM NOR FLASH
C23  .1uF  [c402-25]
C241  .1uF  [c402-25]
C251  .1uF  [c402-25]
R46  10K  [r402-25]
R364  10K  [r402-25]
R370  10K  [r201-6p6spc]
R375  1K  [r201-6p6spc]
R376  10K  [r402-25]
R379  10K  [r402-25]
R381  1K  [r201-6p6spc]
R385  10K  [r402-25]
R388  1K  [r201-6p6spc]
R390  1K  [r201-6p6spc]
R391  10K  [r402-25]
R394  10K  [r201-6p6spc]
R395  10K  [r201-6p6spc]
R396  10K  [r201-6p6spc]
R397  10K  [r201-6p6spc]
R398  1K  [r201-6p6spc]
R400  10K  [r201-6p6spc]
R401  1K  [r201-6p6spc]
R402  1K  [r201-6p6spc]
R403  1K  [r201-6p6spc]
RU82  74CBTLV1G125CRG4  [dck-5]
U83  S29GL512S10TFI010  [tsop56-12x75]
sheet SH39 - MEM eMMC
C269  0.1uF  [c402-25]
C273  4.7uF  [c402-25]
C274  0.22uF  [c402-25]
C280  2.2uF  [c402-25]
C290  0.22uF  [c402-25]
C698  2.2uF  [c402-25]
C703  .1uF  [c402-25]
R404  47K  [r402-25]
R405  47K  [r402-25]
R406  47K  [r402-25]
R407  0  [r402-25]
R410  47K  [r402-25]
R414  47K  [r402-25]
R417  47K  [r402-25]
R422  47K  [r402-25]
R423  47K  [r402-25]
R426  47K  [r402-25]
R427  0  [r402-25]
R428  47K  [r402-25]
R429  0  [r402-25]
R433  NO-POP  [r402-25]
R798  NP  [r402-25]
U14  MTFC8GLWDM-3M AIT Z  [fbga153-169-p5-combo]
U143  SN74LVC1G125DCKR  [dck-5]
sheet SH40 - MEM SD CARD
C12  0.1uF  [c402-25]
C14  0.1uF  [c402-25]
C15  0.1uF  [c402-25]
C16  0.1uF  [c402-25]
C233  10uF  [c603-35x45]
C693  0.1uF  [c402-25]
C694  10uF  [c603-35x45]
C695  NO-POP  [c603-35x45]
P14  MicroSD_CARD  [molex-49225-201]
R14  47K  [r402-25]
R15  47K  [r402-25]
R16  47K  [r402-25]
R17  10K  [r402-25]
R18  47K  [r402-25]
R19  47K  [r402-25]
R304  1K  [r402-25]
R327  10K  [r402-25]
R340  33  [r402-25]
R341  33  [r402-25]
R342  33  [r402-25]
R343  33  [r402-25]
R344  33  [r402-25]
R345  33  [r402-25]
R772  10K  [r603-35x45]
R823  NP  [r402-25]
U77  TPD2E001DRL-Q1  [drl5-12x40]
U78  TPD2E001DRL-Q1  [drl5-12x40]
U79  TPD2E001DRL-Q1  [drl5-12x40]
U122  TPD2E001DRL-Q1  [drl5-12x40]
U123  TPS22965DSG  [dsg8-11x20]
sheet SH41 - USB VBUS
C79  10uF  [c603-35x45]
C80  .1uF  [c402-25]
C86  10uF  [c603-35x45]
C87  .1uF  [c402-25]
C325  10uF  [c603-35x45]
C340  10uF  [c603-35x45]
L8  BLM21PG221SN1  [l805-35x60]
L12  BLM21PG221SN1  [l805-35x60]
R154  100K  [r402-25]
R179  100K  [r402-25]
R481  10K  [r402-25]
R532  10K  [r402-25]
R770  10K  [r402-25]
R771  10K  [r402-25]
TP27  TestPoint1  [tp1-18rd8]
TP39  TestPoint1  [tp1-18rd8]
U36  TPS2065D  [so8-25x75]
U43  TPS2065D  [so8-25x75]
sheet SH42 - USB CONNECTORS
C217  0.1uF  [c402-25]
C681  0.1uF  [c201-6p6spc]
C682  0.1uF  [c201-6p6spc]
FL1  DLW21SN121HQ2  [EMI-36X15-DLW21]
FL2  LW21SN900HQ2  [EMI-36X15-DLW21-rdpads]
FL3  LW21SN900HQ2  [EMI-36X15-DLW21-rdpads]
FL4  DLW21SN121HQ2  [EMI-36X15-DLW21]
P2  AU-Y1009_3-AB-R  [usb-ab-f-10pth]
P3  USBMINI_AB  [SAMTEC-MUSB]
R1  10K  [r402-25]
R301  10K  [r402-25]
R302  10K  [r402-25]
R307  10K  [r402-25]
R323  0  [r402-25]
R324  10K  [r402-25]
R325  0  [r402-25]
R326  10K  [r402-25]
SW1  SW DIP-2  [sw2-30x50-tda]
TP1  TestPoint1  [tp1-18rd8]
TP2  TestPoint1  [tp1-18rd8]
TP1019  6p6spc  [6p6spc]
TP1020  6p6spc  [6p6spc]
TP1021  6p6spc  [6p6spc]
TP1022  6p6spc  [6p6spc]
U72  TPD4S014DSQ  [dsq10-son]
U73  TPD4S014DSQ  [dsq10-son]
U124  tpd1e05u06  [dpy-rdpads]
U125  tpd1e05u06  [dpy-rdpads]
U126  tpd1e05u06  [dpy-rdpads]
U127  tpd1e05u06  [dpy-rdpads]
sheet SH43 - USB FTDI UART
C2  .1uF  [c402-25]
C4  .1uF  [c402-25]
C9  4.7uF  [c603-35x45]
C10  .1uF  [c402-25]
C11  .1uF  [c402-25]
C252  0.1uF  [c402-25]
J1  USBMINI_AB  [SAMTEC-MUSB]
L1  BLM18AG221SN1D  [l603-35x45]
R4  10K  [r402-25]
RU5  SN74CBTLV3257PW  [tssop16-14x70]
U2  FT232RQ  [qfn32_5x5]
sheet SH44 - AIC3106
C130  10uF  [c1206-40x70-POL]
C131  .1uF  [c402-25]
C132  .1uF  [c402-25]
C133  4.7uF  [c603-35x45]
C134  .1uF  [c402-25]
C141  .1uF  [c402-25]
C142  .1uF  [c402-25]
C144  10uF  [c1206-40x70-POL]
C151  .1uF  [c402-25]
C152  10uF  [c1206-40x70-POL]
C153  .1uF  [c402-25]
C168  2.2uF  [c603-35x45]
C173  .1uF  [c402-25]
C536  1uF  [c402-25]
C558  .1uF  [c402-25]
C565  .1uF  [c402-25]
C566  .1uF  [c402-25]
C567  .1uF  [c402-25]
C568  .1uF  [c402-25]
C575  NO-POP  [c402-25]
C620  33uF,6.3V  [c1206-40x70p]
C646  33uF,6.3V  [c1206-40x70p]
C647  2.2uF  [c603-35x45]
C648  .1uF  [c402-25]
L19  BLM21PG221SN1D  [l805-35x60]
L21  BLM21PG221SN1D  [l805-35x60]
L22  BLM21PG221SN1D  [l805-35x60]
P10  Mic In  [st_3500]
P11  Line In  [st_3500]
P12  Line Out  [st_3500]
P13  Headphone Out  [st_3500]
R249  NO-POP  [r402-25]
R250  10  [r402-25]
R251  10  [r402-25]
R252  10  [r402-25]
R253  10  [r402-25]
R254  22  [r402-25]
R257  NO-POP  [r402-25]
R260  2K  [r402-25]
R262  NO-POP  [r402-25]
R266  NO-POP  [r402-25]
R281  100  [r402-25]
R287  20K  [r402-25]
R642  20K  [r402-25]
R643  20K  [r402-25]
R644  2K  [r402-25]
R654  2K  [r402-25]
R659  NO-POP  [r402-25]
R664  NO-POP  [r402-25]
R668  NO-POP  [r402-25]
R671  0  [r402-25]
R672  2.2K  [r402-25]
R673  330  [r402-25]
R675  NO-POP  [r402-25]
R696  20K  [r402-25]
R697  100  [r402-25]
R701  20K  [r402-25]
R702  20K  [r402-25]
U55  TPS77018DBVT  [dbv5-27x39]
U59  TLV320AIC3106  [rgz48-11x34]

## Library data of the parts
C166 C167 C176 C181 C208 C209 C626 C634 C642 C653 C660 C661 = CAP_NP_0: Part #: 101587-1220R
C601 = SC10N16V2KX_0: Part #: 101587-1100R
C82 C321 C324 C336 C1059 = CAP: Part #: 101587-1100R
C1060 = CAP_NP_2: Part #: 101782-1223R
R286 R1092 R1094 R1101 = R: Part #: 102145-3600R
R685 R688 = 1KR2F_0: Part #: 102145-3600R
R814 = R: Part #: 101370-4702R
R130 R132 R443 R444 R468 R732 R818 = R: Part #: R0402-NOPOP
R1 R38 R46 R56 R301 R302 R307 R326 R364 R376 R379 R385 R391 R481 R532 R770 R771 R1041 R1042 = R: Part #: 101370-1003R
R37 R325 R407 R429 R726 R729-R731 R733 R1043 R1044 = R: Part #: 101370-0001R
RN3 RN5 RN7 RN12 RN14 RN16 = R-Pak4_0: Part #: 101327-3600R
U1028 = TPS3808G09DBVR_0: Part #: 102020-0009R
C2 C4 C10 C11 C67 C80 C87 C131 C132 C134 C141 C142 C151 C153 C173 C252 C293 C294 C310 C313 C558 C565-C568 C648 C703 C1072 C1073 = CAP_NP: Part #: 101587-1100R
R370 R394-R397 R400 R471 R788 R1039 R1105 R1106 = R: Part #: 103158-1003R
R721 R1110 R1111 R9366 = R: Part #: 103158-0001R
RU96 = SN74CBT16212DGGR_0: Part #: 102693-0001R
U25 U26 U1027 U1033 U1034 = SN74LVC1GU04_1: Part #: 101057-0004R
RU5 RU19 = SN74CBT3257PW_0: Part #: 101670-0001R
RU30 RU93 = SN74CBT16214DGGR_0: Part #: 102513-0001R
RU4 RU40 RU82 = SN74LVC1G125: Part #: 101689-0125R
RU115 = SN74CBTLV3253_0: Part #: 101433-0001R
R17 R128 R131 R327 R442 = RESISTOR: Part #: 101370-1003R
R465 R727 R728 = R: Part #: 101370-1000R
U18 = SPI_EEPROM_1: Part #: 104273-0001R
C24 C241 = CAP_NP_2: Part #: 101587-1100R
C29 C30 C35 = CAPACITOR_NON-POL: Part #: 101587-1101R
U6 = U-NAND-Micron_16bit_Socket_0: Part #: 103066-0002R
C23 C251 = CAP_.1_uF_10%_0603: Part #: 101587-1100R
R375 R381 R388 R390 R398 R401-R403 = R: Part #: 103158-1002R
U83 = AM29LV256M_0: Part #: 104225-0100R
C12 C14-C16 C217 C269 C693 = Cap_100nF_Cermc_16V_10%_603_4: Part #: 101587-1100R
C273 = CAP: Part #: 103649-0470R
C274 C290 = Cap_100nF_Cermc_16V_10%_603_4: Part #: 101587-1220R
C280 C698 = CAP: Part #: 103649-0220R
R14-R16 R18 R19 R404-R406 R410 R414 R422 R423 R426 R428 = RESISTOR: Part #: 101370-4703R
R417 = R: Part #: 101370-4703R
R427 = RESISTOR: Part #: 101370-0001R
R433 R823 = RESISTOR: Part #: R0402-NOPOP
R798 = R: Part #: r0402-nopop
U14 = MTFC16GJVEC-4M-169WFBGA: Part #: 104412-0008R
U143 = SN74LVC1G125: Part #: 101057-0125R
C79 C86 C233 C325 C340 C694 = CAP: Part #: 102963-0101R
C695 = CAP: Part #: C0603-NOPOP
P14 = MM_CARD_0: Part #: 103053-0001R
R304 = RESISTOR: Part #: 101370-1002R
R340-R345 = RESISTOR: Part #: 101370-3300R
R772 = RESISTOR: Part #: 100687-1003R
U77-U79 U122 = TPDE0001RSE_0: Part #: 102728-0001R
U123 = TPS22965DSG: Part #: 104267-0001R
L8 L12 = INDUCTOR_3: Part #: 101228-2201R
R154 R179 = R: Part #: 101370-1004R
TP1 TP2 TP27 TP39 = TestPoint1_0: Part #: TP-18RD8-NO-POP
U36 U43 = tps2061_1: Part #: 102810-0001R
C681 C682 = CAP_NP_2: Part #: 103241-1100R
FL1 FL4 = DLW21SN121HQ2: Part #: 104184-1201R
FL2 FL3 = DLW21SN121HQ2: Part #: 104184-9000R
P2 = AU-Y1009_3-AB-R: Part #: 104383-0001R
J1 P3 = USBMINI_B_0: Part #: 101956-0001R
R323 = RESISTOR_0: Part #: 101370-0001R
R324 = RESISTOR_0: Part #: 101370-1003R
SW1 = SW_DIP-2: Part #: 101184-0002R
TP1019-TP1022 = TEST_POINT_0: Part #: no-pop
U72 U73 = TPD4S014DSQ: Part #: 104147-0001R
U124-U127 = tpd1e05u06: Part #: 104410-0001R
C9 C133 = CAP_NP_2: Part #: 102590-0470R
L1 = FERRITE_CHIP_0: Part #: 101858-2201R
R4 = R_0: Part #: 101370-1003R
U2 = FT232RQ_7: Part #: 103625-0001R
C130 C144 C152 = CAPACITOR_POL_0: Part #: 101003-0101R
C168 C647 = CAP: Part #: 102965-0220R
C536 = C_0: Part #: 102962-0100R
C575 = CAP_NP: Part #: C0402-NOPOP
C620 C646 = CAPACITOR_POL_0: Part #: 101953-0331R
L19 L21 L22 = INDUCTOR: Part #: 101228-2201R
P10-P13 = Kycon_ST-3500_0: Part #: 101012-0001R
R249 R257 R262 R266 R659 R664 R668 R675 = R_0: Part #: R0402-NOPOP
R250-R253 = R_0: Part #: 101370-1000R
R254 = RESISTOR: Part #: 101370-2200R
R260 R644 R654 = R_0: Part #: 102145-2002R
R281 R697 = R: Part #: 101370-1001R
R287 R642 R643 R696 R701 R702 = R_0: Part #: 101370-2003R
R671 = R_0: Part #: 101370-0001R
R672 = R_0: Part #: 101370-2202R
R673 = R_0: Part #: 101370-3301R
U55 = TPS76901_1: Part #: 101320-0018R
U59 = TLV320AIC3106_0: Part #: 102800-0001R

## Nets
GND: C2.2 C4.2 C9.2 C10.2 C11.2 C12.2 C14.2 C15.2 C16.2 C23.2 C24.2 C29.2 C30.2 C35.2 C67.2 C79.2 C80.2 C82.2 C86.2 C87.2 C130.2 C131.2 C132.2 C133.2 C134.2 C141.2 C142.2 C144.2 C151.2 C152.2 C153.2 C217.2 C233.2 C241.2 C251.2 C252.2 C269.2 C273.2 C274.2 C280.2 C290.2 C293.2 C294.2 C310.2 C313.2 C321.2 C324.2 C325.2 C336.2 C340.2 C536.2 C565.2 C566.2 C567.2 C568.2 C575.2 C693.2 C694.2 C695.2 C698.2 C703.1 C1059.2 C1060.2 C1072.2 C1073.2 J1.5(USBVSS) J1.6(SHIELD1) J1.7(SHIELD2) J1.8(SHIELD3) J1.9(SHIELD4) P2.5(USBVSS) P2.8(CON8) P2.11(SHIELD1) P2.12(SHIELD2) P2.13(SHIELD3) P2.14(SHIELD4) P2.15(SHIELD5) P2.16(SHIELD6) P3.5(USBVSS) P3.6(SHIELD1) P3.7(SHIELD2) P3.8(SHIELD3) P3.9(SHIELD4) P10.1(SHIELD) P10.4(TIPB) P11.1(SHIELD) P11.4(TIPB) P12.1(SHIELD) P13.1(SHIELD) P14.6(VSS) R154.2 R179.2 R257.2 R260.2 R262.2 R266.2 R287.2 R304.2 R323.2 R325.2 R370.1 R375.1 R381.1 R388.1 R390.1 R394.1 R395.1 R396.1 R397.1 R398.1 R400.1 R401.1 R402.1 R403.1 R481.1 R532.1 R642.2 R643.2 R644.2 R675.2 R696.2 R701.2 R702.2 R721.2 R814.2 R1042.2 R1110.1 R1111.2 RU4.3(GND) RU5.8(GND) RU5.10(3B2) RU5.11(3B1) RU5.13(4B2) RU5.14(4B1) RU5.15(~{OE}) RU19.8(GND) RU19.15(~{OE}) RU30.8(GND.1) RU30.19(GND.2) RU30.38(GND.3) RU30.49(GND.4) RU40.1(OE) RU40.3(GND) RU82.3(GND) RU93.8(GND.1) RU93.19(GND.2) RU93.38(GND.3) RU93.49(GND.4) RU96.8(GND.1) RU96.19(GND.2) RU96.38(GND.3) RU96.49(GND.4) RU115.8(GND) U2.4(GND.1) U2.17(GND.2) U2.20(GND.3) U2.24(AGND) U2.26(TEST) U2.33(PWRPAD) U6.13(GND1) U6.25(GND2) U6.36(GND3) U6.48(GND4) U14.C4(VSS.1) U14.E7(VSS.2) U14.G5(VSS.3) U14.H10(VSS.4) U14.K8(VSS.5) U14.N2(VSS.6) U14.N5(VSS.7) U14.P4(VSS.8) U14.P6(VSS.9) U18.10(VSS) U25.3(GND) U26.3(GND) U36.1(GND) U43.1(GND) U55.2(GND) U55.3(ENn) U59.15(AVSS_ADC) U59.20(DRVSS.1) U59.21(DRVSS.2) U59.26(AVSS_DAC) U59.42(DVSS) U59.49(TPAD) U72.8(GND) U72.11(PWR_PAD) U73.8(GND) U73.11(PWR_PAD) U77.4(GND) U78.4(GND) U79.4(GND) U83.33(VSS1) U83.52(VSS2) U122.4(GND) U123.5(GND) U123.9(PWR_PAD) U124.2(GND) U125.2(GND) U126.2(GND) U127.2(GND) U143.2(I) U143.3(GND) U1027.3(GND) U1028.2(GND) U1033.3(GND) U1034.3(GND) ; also on sheet 3 5 7 10 11 12 13 14 15 16 17 18 20 21 22 35 36 37 38 39 40 41 42 43 44 45 46 47 48 49 50 51 52 53 54 55 56 57 58 59 62 63 64 65 66 67 68 69 70 71
VIN2_S0: R1039.1 RU19.1(S) RU30.1(S0) U25.2(I) ; also on sheet 42
VIN2_S1: RU30.56(S1) U25.4(O)
VIN2_S2: R788.1 U1027.2(I) ; also on sheet 42
VIN2_S2N: RU30.55(S2) U1027.4(O)
VIN2A_MDIO_D: RU115.10(2B1) ; also on sheet 65
VIN2A_MDIO_MCLK: RU115.6(1B1) ; also on sheet 65
VIN[2]A_CLK: RU19.2(1B1) ; also on sheet 50
VIN[2]A_D[0]: RU30.53(1B2) ; also on sheet 50
VIN[2]A_D[1]: RU30.51(2B2) ; also on sheet 50
VIN[2]A_D[2]: RU30.48(3B2) ; also on sheet 50
VIN[2]A_D[3]: RU30.46(4B2) ; also on sheet 50
VIN[2]A_D[4]: RU30.44(5B2) ; also on sheet 50
VIN[2]A_D[5]: RU30.42(6B2) ; also on sheet 50
VIN[2]A_D[6]: RU30.40(7B2) ; also on sheet 50
VIN[2]A_D[7]: RU30.37(8B2) ; also on sheet 50
VIN[2]A_D[8]: RU30.35(9B2) ; also on sheet 50
VIN[2]A_D[9]: RU30.33(10B2) ; also on sheet 50
VIN[2]A_D[10]: RU115.5(1B2) ; also on sheet 50
VIN[2]A_D[11]: RU115.11(2B2) ; also on sheet 50
VIN[2]A_D[12]: RU93.53(1B2) ; also on sheet 50
VIN[2]A_D[13]: RU93.51(2B2) ; also on sheet 50
VIN[2]A_D[14]: RU93.48(3B2) ; also on sheet 50
VIN[2]A_D[15]: RU93.46(4B2) ; also on sheet 50
VIN[2]A_D[16]: RU93.44(5B2) ; also on sheet 50
VIN[2]A_D[17]: RU93.42(6B2) ; also on sheet 50
VIN[2]A_D[18]: RU93.40(7B2) ; also on sheet 50
VIN[2]A_D[19]: RU93.37(8B2) ; also on sheet 50
VIN[2]A_D[20]: RU93.35(9B2) ; also on sheet 50
VIN[2]A_D[21]: RU93.33(10B2) ; also on sheet 50
VIN[2]A_D[22]: RU93.31(11B2) ; also on sheet 50
VIN[2]A_D[23]: RU93.29(12B2) ; also on sheet 50
VIN[2]A_DE0: RU19.5(2B1) ; also on sheet 50
VIN[2]A_FLD0: RU40.4(O) ; also on sheet 50
VIN[2]A_HSYNC: RU19.11(3B1) ; also on sheet 50
VIN[2]A_VSYNC: RU19.14(4B1) ; also on sheet 50
AIC3106_MCLK: R254.1 ; also on sheet 2
AIC_AVDD_DAC3.3: C141.1 C142.1 C144.1 L21.1 U59.25(AVDD_DAC)
AIC_BCLK: R253.2 R642.1 U59.38(BCLK)
AIC_DIN: R251.2 R643.1 U59.40(DIN)
AIC_DOUT: R250.2 U59.41(DOUT)
AIC_DRVDD3.3: C151.1 C152.1 C565.1 C566.1 C567.1 L22.1 U59.16(DRVDD.1) U59.17(DRVDD.2) U59.24(DRVDD.3)
AIC_DVDD3.3: C133.1 C134.1 U55.5(OUT) U59.36(DVDD.1)
AIC_IOVDD3.3: C130.1 C132.1 L19.2 U59.44(IOVDD)
AIC_MCA3_ACLKX: R253.1 ; also on sheet 66
AIC_MCA3_AFSX: R252.1 ; also on sheet 66
AIC_MCA3_AXR0: R251.1 ; also on sheet 66
AIC_MCA3_AXR1: R250.1 ; also on sheet 66
AIC_WCLK: R252.2 U59.39(WCLK)
AQSPI1_CS[0]: R731.1 ; also on sheet 4
AQSPI1_D[0]: R729.1 ; also on sheet 4
AQSPI1_D[1]: R730.2 ; also on sheet 4
AQSPI1_D[2]: R733.2 ; also on sheet 4
AQSPI1_D[3]: R726.1 ; also on sheet 4
AQSPI1_RTCLK: R727.2 ; also on sheet 4
AQSPI1_SCLK: R727.1 R728.2 ; also on sheet 4
B_QSPI1_SCLK: R465.1 R468.2 ; also on sheet 70
C_GPMC_A0: RU96.20(8A2) ; also on sheet 4 63
C_GPMC_CLK: RU96.5(2A2) ; also on sheet 4
C_GPMC_nCS2: RU96.12(5A2) ; also on sheet 4 70
C_GPMC_nCS3: RU96.14(6A2) ; also on sheet 4 68
C_VIN[2]A_CLK: RU19.4(1A) ; also on sheet 9
C_VIN[2]A_D[0]: RU30.2(1A) ; also on sheet 9
C_VIN[2]A_D[1]: RU30.4(2A) ; also on sheet 9
C_VIN[2]A_D[2]: RU30.6(3A) ; also on sheet 9
C_VIN[2]A_D[3]: RU30.9(4A) ; also on sheet 9
C_VIN[2]A_D[4]: RU30.11(5A) ; also on sheet 9
C_VIN[2]A_D[5]: RU30.13(6A) ; also on sheet 9
C_VIN[2]A_D[6]: RU30.15(7A) ; also on sheet 9
C_VIN[2]A_D[7]: RU30.18(8A) ; also on sheet 9
C_VIN[2]A_D[8]: RU30.21(9A) ; also on sheet 9
C_VIN[2]A_D[9]: RU30.23(10A) ; also on sheet 9
C_VIN[2]A_D[10]: RU115.7(1A) ; also on sheet 9
C_VIN[2]A_D[11]: RU115.9(2A) ; also on sheet 9
C_VIN[2]A_D[12]: RU93.2(1A) ; also on sheet 9
C_VIN[2]A_D[13]: RU93.4(2A) ; also on sheet 9
C_VIN[2]A_D[14]: RU93.6(3A) ; also on sheet 9
C_VIN[2]A_D[15]: RU93.9(4A) ; also on sheet 9
C_VIN[2]A_D[16]: RU93.11(5A) ; also on sheet 9
C_VIN[2]A_D[17]: RU93.13(6A) ; also on sheet 9
C_VIN[2]A_D[18]: RU93.15(7A) ; also on sheet 9
C_VIN[2]A_D[19]: RU93.18(8A) ; also on sheet 9
C_VIN[2]A_D[20]: RU93.21(9A) ; also on sheet 9
C_VIN[2]A_D[21]: RU93.23(10A) ; also on sheet 9
C_VIN[2]A_D[22]: RU93.25(11A) ; also on sheet 9
C_VIN[2]A_D[23]: RU93.27(12A) ; also on sheet 9
C_VIN[2]A_DE0: RU19.7(2A) ; also on sheet 9
C_VIN[2]A_FLD0: R9366.2 RU40.2(I) ; also on sheet 9
C_VIN[2]A_HSYNC0: RU19.9(3A) ; also on sheet 9
C_VIN[2]A_VSYNC0: RU19.12(4A) ; also on sheet 9
CAMERA_CLK: RU19.3(1B2) ; also on sheet 40
CAMERA_D0: RU30.3(1B3) ; also on sheet 40
CAMERA_D1: RU30.5(2B3) ; also on sheet 40
CAMERA_D2: RU30.7(3B3) ; also on sheet 40
CAMERA_D3: RU30.10(4B3) ; also on sheet 40
CAMERA_D4: RU30.12(5B3) ; also on sheet 40
CAMERA_D5: RU30.14(6B3) ; also on sheet 40
CAMERA_D6: RU30.16(7B3) ; also on sheet 40
CAMERA_D7: RU30.20(8B3) ; also on sheet 40
CAMERA_D8: RU30.22(9B3) ; also on sheet 40
CAMERA_D9: RU30.24(10B3) ; also on sheet 40
CAMERA_D10: RU115.4(1B3) ; also on sheet 40
CAMERA_D11: RU115.12(2B3) ; also on sheet 40
CAMERA_D12: RU93.3(1B3) ; also on sheet 40
CAMERA_D13: RU93.5(2B3) ; also on sheet 40
CAMERA_HSYNC: RU19.10(3B2) ; also on sheet 40
CAMERA_VSYNC: RU19.13(4B2) ; also on sheet 40
CON.PCIE_RXN1: TP1020.1 ; also on sheet 36
CON.PCIE_RXP1: TP1019.1 ; also on sheet 36
CON.PCIE_TXN1: TP1022.1 ; also on sheet 36
CON.PCIE_TXP1: TP1021.1 ; also on sheet 36
CON_MMC1_CLK: P14.5(CLK) R17.2 R343.2 U78.3(IO1)
CON_MMC1_CMD: P14.3(CMD) R16.2 R344.2 U78.5(IO2)
CON_MMC1_DAT0: P14.7(DAT0) R18.2 R342.2 U77.5(IO2)
CON_MMC1_DAT1: P14.8(DAT1) R19.2 R341.2 U77.3(IO1)
CON_MMC1_DAT2: P14.1(DAT2) R14.2 R340.2 U79.5(IO2)
CON_MMC1_DAT3: P14.2(DAT3) R15.2 R345.2 U79.3(IO1)
CONN_USB1_DM: FL1.3 P2.2(D-) U73.6(D-)
CONN_USB1_DP: FL1.2 P2.3(D+) U73.7(D+)
CONN_USB2_DM: FL4.3 P3.2(D-) U72.6(D-)
CONN_USB2_DP: FL4.2 P3.3(D+) U72.7(D+)
CONN_USB_D+: J1.3(D+) U2.14(USBDP)
CONN_USB_D-: J1.2(D-) U2.15(USBDM)
CONN_USB_RXN0: FL3.3 P2.9(CON9) U124.1(IO)
CONN_USB_RXP0: FL3.2 P2.10(CON10) U125.1(IO)
CONN_USB_TXN0: FL2.3 P2.6(CON6) U126.1(IO)
CONN_USB_TXP0: FL2.2 P2.7(CON7) U127.1(IO)
DDR1_A0: RN14.1(R1A) ; also on sheet 5 19 20 21
DDR1_A1: RN16.4(R4A) ; also on sheet 5 19 20 21
DDR1_A2: RN5.3(R3A) ; also on sheet 5 19 20 21
DDR1_A3: RN5.1(R1A) ; also on sheet 5 19 20 21
DDR1_A4: RN5.4(R4A) ; also on sheet 5 19 20 21
DDR1_A5: RN5.2(R2A) ; also on sheet 5 19 20 21
DDR1_A6: RN7.3(R3A) ; also on sheet 5 19 20 21
DDR1_A7: RN16.3(R3A) ; also on sheet 5 19 20 21
DDR1_A8: RN16.1(R1A) ; also on sheet 5 19 20 21
DDR1_A9: RN7.1(R1A) ; also on sheet 5 19 20 21
DDR1_A10: RN3.1(R1A) ; also on sheet 5 19 20 21
DDR1_A11: RN7.2(R2A) ; also on sheet 5 19 20 21
DDR1_A12: RN14.3(R3A) ; also on sheet 5 19 20 21
DDR1_A13: RN16.2(R2A) ; also on sheet 5 19 20 21
DDR1_A14: RN7.4(R4A) ; also on sheet 5 19 20 21
DDR1_A15: RN3.3(R3A) ; also on sheet 5 19 20 21
DDR1_BA0: RN12.3(R3A) ; also on sheet 5 19 20 21
DDR1_BA1: RN14.2(R2A) ; also on sheet 5 19 20 21
DDR1_BA2: RN14.4(R4A) ; also on sheet 5 19 20 21
DDR1_CASN: RN12.2(R2A) ; also on sheet 5 19 20 21
DDR1_CKE: R814.1 R1101.1 ; also on sheet 5 19 20 21
DDR1_CLK0: R685.1 ; also on sheet 5 19 20 21
DDR1_CLK0N: R688.1 ; also on sheet 5 19 20 21
DDR1_CSN0: RN12.1(R1A) ; also on sheet 5 19 20 21
DDR1_CSN1: R1094.1 ; also on sheet 5 19 20 21
DDR1_ODT0: RN3.2(R2A) ; also on sheet 5 19 20 21
DDR1_ODT1: R1092.1 ; also on sheet 5 19 20 21
DDR1_RASN: R286.1 ; also on sheet 5 19 20 21
DDR1_RST: R818.1 R1044.2 ; also on sheet 20 21
DDR1_WEN: RN3.4(R4A) ; also on sheet 5 19 20 21
EMAC[1]_RXC: RU93.41(7B1) ; also on sheet 48
EMAC[1]_RXCTL: RU93.39(8B1) ; also on sheet 48
EMAC[1]_RXD0: RU93.30(12B1) ; also on sheet 48
EMAC[1]_RXD1: RU93.32(11B1) ; also on sheet 48
EMAC[1]_RXD2: RU93.34(10B1) ; also on sheet 48
EMAC[1]_RXD3: RU93.36(9B1) ; also on sheet 48
EMAC[1]_TXC: RU93.54(1B1) ; also on sheet 48
EMAC[1]_TXCTL: RU93.52(2B1) ; also on sheet 48
EMAC[1]_TXD0: RU93.43(6B1) ; also on sheet 48
EMAC[1]_TXD1: RU93.45(5B1) ; also on sheet 48
EMAC[1]_TXD2: RU93.47(4B1) ; also on sheet 48
EMAC[1]_TXD3: RU93.50(3B1) ; also on sheet 48
EVM_1V8: R407.2 ; also on sheet 37 40 44 45 46 50 55 57 59
EVM_3V3: C10.1 C11.1 C23.1 C24.1 C29.1 C30.1 C35.1 C67.1 C131.1 C153.1 C241.1 C251.1 C252.1 C293.1 C294.1 C310.1 C313.1 C324.1 C336.1 C536.1 C694.1 C703.2 C1072.1 C1073.1 L19.1 L21.2 L22.2 R1.2 R4.1 R38.2 R46.2 R56.2 R128.1 R131.2 R249.1 R301.2 R302.2 R307.2 R324.1 R326.1 R364.2 R376.1 R379.1 R385.2 R391.1 R429.2 R442.1 R471.1 R654.1 R659.1 R664.1 R668.1 R770.2 R771.2 R772.1 R788.2 R798.2 R1039.2 R1105.2 R1106.2 RU4.5(VCC) RU5.16(VCC) RU19.16(VCC) RU40.5(VCC) RU82.5(VCC) RU96.17(VCC.1) RU96.56(S1) RU115.16(VCC) U2.1(VCCIO.1) U6.12(VCC) U6.34(VCC2) U6.37(VCC3) U6.39(VCC4) U18.2(VCC) U18.14(VIO/RFU) U25.5(VCC) U26.5(VCC) U55.1(IN) U83.29(VIO) U83.43(VCC) U123.1(VIN.1) U123.2(VIN.2) U143.5(VCC) U1027.5(VCC) U1033.5(VCC) U1034.5(VCC) ; also on sheet 3 4 10 11 35 36 37 38 39 40 42 43 44 45 46 47 48 49 50 51 55 56 58 59 62 63 65 66 67 69 70
EVM_3V3_SD: C12.1 C14.1 C15.1 C16.1 C233.1 P14.4(VDD) R823.1 U77.1(VCC) U78.1(VCC) U79.1(VCC) U123.7(VOUT.2) U123.8(VOUT.1)
EVM_5V0: C82.1 C321.1 C325.1 C340.1 RU30.17(VCC.1) RU93.17(VCC.1) U36.2(IN1) U36.3(IN2) U43.2(IN1) U43.3(IN2) U123.4(VBIAS) ; also on sheet 36 37 38 40 41 45 50 54 55 58 63 68
EVM_VDD_DDR: C166.2 C167.2 C176.2 C181.2 C208.2 C209.2 C601.2 C626.2 C634.2 C642.2 C653.2 C660.2 C661.2 R1041.1 R1043.1 ; also on sheet 20 21 22 55 56 57 59
EXVIN2_S0: R1105.1 RU93.1(S0) U1033.2(I) ; also on sheet 42
EXVIN2_S0N: RU93.56(S1) RU115.14(S0) U1033.4(O)
EXVIN2_S2: R1106.1 U1034.2(I) ; also on sheet 42
EXVIN2_S2N: RU93.55(S2) RU115.2(S1) U1034.4(O)
FLASH_BYTE: R391.2 U83.53(~{BYT}E)
FLASH_WP: R379.2 U83.16(~{WP}/ACC)
FTDI_UARTIN: RU5.4(1A) U2.2(RXD)
FTDI_UARTOUT: RU5.7(2A) U2.30(TXD)
GP2[27]: RU96.10(4A2) ; also on sheet 4 50
GPMC_A1: U83.31(A0) ; also on sheet 63
GPMC_A2: U83.26(A1) ; also on sheet 63
GPMC_A3: U83.25(A2) ; also on sheet 63
GPMC_A4: U83.24(A3) ; also on sheet 63
GPMC_A5: U83.23(A4) ; also on sheet 63
GPMC_A6: U83.22(A5) ; also on sheet 63
GPMC_A7: U83.21(A6) ; also on sheet 63
GPMC_A8: U83.20(A7) ; also on sheet 68
GPMC_A9: U83.10(A8) ; also on sheet 68
GPMC_A10: U83.9(A9) ; also on sheet 68
GPMC_A11: U83.8(A10) ; also on sheet 68
GPMC_A12: U83.7(A11) ; also on sheet 68
GPMC_A13: R394.2 U83.6(A12) ; also on sheet 70
GPMC_A14: R396.2 U83.5(A13) ; also on sheet 70
GPMC_A15: R397.2 U83.4(A14) ; also on sheet 70
GPMC_A16: R400.2 U83.3(A15) ; also on sheet 70
GPMC_A17: R395.2 U83.54(A16) ; also on sheet 70
GPMC_A18: R370.2 U83.19(A17) ; also on sheet 70
GPMC_A19: RU96.2(1A1) ; also on sheet 70
GPMC_A20: RU96.4(2A1) ; also on sheet 70
GPMC_A21: RU96.6(3A1) ; also on sheet 70
GPMC_A22: RU96.9(4A1) ; also on sheet 70
GPMC_A23: RU96.11(5A1) ; also on sheet 70
GPMC_A24: RU96.13(6A1) ; also on sheet 70
GPMC_A25: RU96.15(7A1) ; also on sheet 70
GPMC_A26: RU96.18(8A1) ; also on sheet 70
GPMC_ADVn_ALE: RU96.3(1A2) ; also on sheet 4
GPMC_BE0n_CLE: RU96.7(3A2) ; also on sheet 4
GPMC_D00: U6.29(I/O0) U83.35(DQ0) ; also on sheet 43 59 63
GPMC_D01: U6.30(I/O1) U83.37(DQ1) ; also on sheet 43 59 63
GPMC_D02: U6.31(I/O2) U83.39(DQ2) ; also on sheet 43 59 63
GPMC_D03: U6.32(I/O3) U83.41(DQ3) ; also on sheet 43 59 63
GPMC_D04: U6.41(I/O4) U83.44(DQ4) ; also on sheet 43 59 63
GPMC_D05: U6.42(I/O5) U83.46(DQ5) ; also on sheet 43 59 63
GPMC_D06: U6.43(I/O6) U83.48(DQ6) ; also on sheet 43 63
GPMC_D07: U6.44(I/O7) U83.50(DQ7) ; also on sheet 43 63
GPMC_D08: U6.26(I/O8) U83.36(DQ8) ; also on sheet 43 63
GPMC_D09: U6.27(I/O9) U83.38(DQ9) ; also on sheet 43 63
GPMC_D10: U6.28(I/O10) U83.40(DQ10) ; also on sheet 43 63
GPMC_D11: U6.33(I/O11) U83.42(DQ11) ; also on sheet 43 63
GPMC_D12: U6.40(I/O12) U83.45(DQ12) ; also on sheet 43 63
GPMC_D13: U6.45(I/O13) U83.47(DQ13) ; also on sheet 43 63
GPMC_D14: U6.46(I/O14) U83.49(DQ14) ; also on sheet 43 63
GPMC_D15: U6.47(I/O15) U83.51(DQ15/A-1) ; also on sheet 43 63
GPMC_nCS0: RU4.2(I) RU82.2(I) ; also on sheet 4
GPMC_OEN_REN: R46.1 U6.8(\\~{R}E) U83.34(~{OE}) ; also on sheet 4
GPMC_WAIT: RU96.16(7A2) ; also on sheet 4
GPMC_WEn: R385.1 U6.18(\\~{W}E) U83.13(~{WE}) ; also on sheet 4
GPMC_WPN: U6.19(\\~{W}P) ; also on sheet 43
I2C1_SCL: U59.1(SCL) ; also on sheet 3 37 42 45 50 56 62 69
I2C1_SDA: U59.2(SDA) ; also on sheet 3 37 42 45 50 56 62 69
J6_VDDSHV8: R14.1 R15.1 R16.1 R17.1 R18.1 R19.1 R327.1 ; also on sheet 13 58
J6E_DDR1_RST: R818.2 ; also on sheet 5
MMC1_CLK: R343.1 ; also on sheet 61
MMC1_CMD: R344.1 ; also on sheet 61
MMC1_DAT0: R342.1 ; also on sheet 61
MMC1_DAT1: R341.1 ; also on sheet 61
MMC1_DAT2: R340.1 ; also on sheet 61
MMC1_DAT3: R345.1 ; also on sheet 61
MMC1_SD_CD: P14.9(INSERT) R327.2 U122.5(IO2) ; also on sheet 61
MMC2_CLK: R427.1 R433.2 ; also on sheet 70
MMC2_CMD: R410.2 U14.M5(CMD) ; also on sheet 70
MMC2_DAT0: R404.2 U14.A3(DAT0) ; also on sheet 70
MMC2_DAT1: R422.2 U14.A4(DAT1) ; also on sheet 70
MMC2_DAT2: R426.2 U14.A5(DAT2) ; also on sheet 70
MMC2_DAT3: R406.2 U14.B2(DAT3) ; also on sheet 70
MMC2_DAT4: R405.2 U14.B3(DAT4) ; also on sheet 70
MMC2_DAT5: R414.2 U14.B4(DAT5) ; also on sheet 70
MMC2_DAT6: R423.2 U14.B5(DAT6) ; also on sheet 70
MMC2_DAT7: R428.2 U14.B6(DAT7) ; also on sheet 70
MMC2_VCCQ: C274.1 C280.1 R404.1 R405.1 R406.1 R407.1 R410.1 R414.1 R417.2 R422.1 R423.1 R426.1 R428.1 R433.1 R798.1 U14.C6(VDD.1) U14.M4(VDD.2) U14.N4(VDD.3) U14.P3(VDD.4) U14.P5(VDD.5)
MMC2_VDDI: C269.1 C698.1 U14.C2(VDDI.1)
MMC2_VFF: C273.1 C290.1 R429.1 U14.E6(VFF.1) U14.F5(VFF.2) U14.J10(VFF.3) U14.K9(VFF.4)
MMC_PWR_ON: R772.2 U123.3(ON) ; also on sheet 42
NAND_GPMC_ADVn_ALE: RU96.53(1B2) U6.17(ALE)
NAND_GPMC_BE0n_CLE: RU96.48(3B2) U6.16(CLE)
NAND_GPMC_WAIT: R37.1 RU96.40(7B2)
NAND_SELn: RU4.1(OE) ; also on sheet 42 43
NOR_ALT_ADDRn: R471.2 RU96.55(S2) U26.2(I) ; also on sheet 42 43
NOR_CEn: R364.1 RU82.4(O) U83.32(~{CE})
NOR_GPMC_A19: R375.2 RU96.54(1B1) U83.18(A18)
NOR_GPMC_A20: R390.2 RU96.52(2B1) U83.11(A19)
NOR_GPMC_A21: R388.2 RU96.50(3B1) U83.12(A20)
NOR_GPMC_A22: R381.2 RU96.47(4B1) U83.15(A21)
NOR_GPMC_A23: R403.2 RU96.45(5B1) U83.2(A22)
NOR_GPMC_A24: R402.2 RU96.43(6B1) U83.1(A23)
NOR_GPMC_A25: R401.2 RU96.41(7B1) U83.56(A24)
NOR_GPMC_A26: R398.2 RU96.39(8B1) U83.55(A25/NC4)
NOR_SELn: RU82.1(OE) ; also on sheet 42 43
PCF8575_INT: R9366.1 ; also on sheet 42 50
QSPI1_CS[0]: R732.1 ; also on sheet 70
QSPI1_D[0]: R444.1 ; also on sheet 70
QSPI1_D[1]: R132.2 ; also on sheet 70
QSPI1_D[2]: R443.2 ; also on sheet 70
QSPI1_D[3]: R130.1 ; also on sheet 70
QSPI1_RTCLK: R465.2 ; also on sheet 70
R_QSPI1_CS[0]: R131.1 R731.2 R732.2 U18.7(~{CS})
R_QSPI1_D[0]: R444.2 R729.2 U18.15(SI/IO0)
R_QSPI1_D[1]: R132.1 R730.1 U18.8(SO/IO1)
R_QSPI1_D[2]: R442.2 R443.1 R733.1 U18.9(~{WP}/IO2)
R_QSPI1_D[3]: R128.2 R130.2 R726.2 U18.1(~{HOLD}/IO3)
R_QSPI1_SCLK: R468.1 R728.1 U18.16(SCLK)
RSTOUTn: U18.3(~{RESET}/RFU) U59.33(~{RESET}) U83.14(~{RESET}) U143.1(OE) ; also on sheet 3 11 35 40 56 59
UART1_RXD: RU5.5(2B1) ; also on sheet 62
UART1_TXD: RU5.2(1B1) ; also on sheet 62
UART3_RXD_BOOT: RU5.6(2B2) ; also on sheet 62
UART3_TXD_BOOT: RU5.3(1B2) ; also on sheet 62
UART_SEL1_3: RU5.1(S) ; also on sheet 42 43
USB1_DM: FL1.4 ; also on sheet 64
USB1_DP: FL1.1 ; also on sheet 64
USB1_DRV_VBUS: R481.2 U36.4(EN) ; also on sheet 64
USB1_ID: P2.4(ID) R326.2 SW1.2(A2) U73.5(ID) ; also on sheet 42
USB1_VBUS: C80.1 L8.1 P2.1(USBVDD) U73.9(VBUS.2) U73.10(VBUS.1)
USB1_VBUS_OCN: R771.1 TP27.1 U36.5(OCn) ; also on sheet 42
USB2_DM: FL4.4 ; also on sheet 64
USB2_DP: FL4.1 ; also on sheet 64
USB2_DRV_VBUS: R532.2 U43.4(EN) ; also on sheet 64
USB2_ID: P3.4(ID) R324.2 SW1.1(A1) U72.5(ID) ; also on sheet 42
USB2_VBUS: C87.1 C217.1 L12.1 P3.1(USBVDD) U72.9(VBUS.2) U72.10(VBUS.1)
USB2_VBUS_OCN: R770.1 TP39.1 U43.5(OCn) ; also on sheet 42
USB_AC_TXN0: C682.2 FL2.4
USB_AC_TXP0: C681.2 FL2.1
USB_RXN0: FL3.4 ; also on sheet 64
USB_RXP0: FL3.1 ; also on sheet 64
USB_TXN0: C682.1 ; also on sheet 64
USB_TXP0: C681.1 ; also on sheet 64
VSYS_3V3: C1059.1 U1028.6(VDD) ; also on sheet 11 36 46 52 54 55 56 57 58
VTT: C166.1 C167.1 C176.1 C181.1 C208.1 C209.1 C626.1 C634.1 C642.1 C653.1 C660.1 C661.1 R286.2 R1092.2 R1094.2 R1101.2 RN3.5(R4B) RN3.6(R3B) RN3.7(R2B) RN3.8(R1B) RN5.5(R4B) RN5.6(R3B) RN5.7(R2B) RN5.8(R1B) RN7.5(R4B) RN7.6(R3B) RN7.7(R2B) RN7.8(R1B) RN12.5(R4B) RN12.6(R3B) RN12.7(R2B) RN12.8(R1B) RN14.5(R4B) RN14.6(R3B) RN14.7(R2B) RN14.8(R1B) RN16.5(R4B) RN16.6(R3B) RN16.7(R2B) RN16.8(R1B) ; also on sheet 55
N18149573: R721.1 RU96.21(9A1) RU96.22(9A2) RU96.23(10A1) RU96.24(10A2) RU96.25(11A1) RU96.26(11A2) RU96.27(12A1) RU96.28(12A2)
N19635642: C693.1 R823.2 U122.1(VCC)
N19667155: C695.1 U123.6(CT)
N21135838: C646.1 U59.23(HPROUT)
N21135844: C646.2 P13.3(RING) R701.1
N21135850: C620.2 P13.2(TIP) R696.1
N21135862: C620.1 U59.18(HPLOUT)
N21135894: C647.2 P12.3(RING) R702.1
N21136021: R249.2 R644.1 U59.43(SELECT)
N21136029: R671.2 U59.11(MIC3L) U59.14(MIC3R)
N21136035: C558.1 C575.1 P10.2(TIP) P10.3(RING) R673.1 R675.1
N21136037: C568.1 R672.1 R673.2
N21136043: R672.2 U59.13(MICBIAS)
N21136051: C558.2 R671.1
N21136104: C173.2 U59.3(LINE1L+)
N21136106: C168.2 P12.2(TIP) R287.1
N21136108: C648.2 U59.5(LINE1R+)
N21136118: R281.1 U59.29(LEFT_LO+)
N21136820: C648.1 P11.3(RING)
N21136935: R254.2 U59.37(MCLK)
N21136965: R266.1 R668.2 U59.48(MFP3)
N21136967: R262.1 R664.2 U59.47(MFP2)
N21136973: R260.1 R659.2 U59.46(MFP1)
N21136977: R257.1 R654.2 U59.45(MFP0)
N21137001: C173.1 P11.2(TIP)
N21137040: C647.1 R697.2
N21137042: R697.1 U59.31(RIGHT_LO+)
N21137044: C168.1 R281.2
N22073312: R427.2 U14.M6(CLK)
N22073335: R417.1 U14.K5(RSTN) U143.4(O)
N22562266: R4.2 U2.11(CBUS3)
N22573042: C4.1 C9.1 L1.2 U2.19(VCC)
N22663792: C2.1 J1.1(USBVDD) L1.1
N22754009: C79.1 L8.2 R154.1 U36.6(OUT3) U36.7(OUT2) U36.8(OUT1)
N23117477: R56.1 RU4.4(O) U6.9(\\~{CE})
N23117517: R37.2 R38.1 U6.7(R~{/B})
N23418969: R1042.1 R1043.2 U1028.5(SENSE1)
N23418979: C1060.1 U1028.4(CT)
N23418983: R1041.2 R1044.1 U1028.1(~{RESE}T)
N23442401: RU96.1(S0) U26.4(O)
N24612745: C601.1 R685.2 R688.2
N25659795: R1110.2 RU30.25(11A) RU30.26(11B3) RU30.27(12A) RU30.28(12B3)
N26265592: R1111.1 RU115.1(1OE) RU115.15(2OE)
N27717584: TP1.1 U72.1(VBUS_OUT.1) U72.2(VBUS_OUT.2)
N27834162: R376.2 U83.17(RY/~{BY})
N27840356: R301.1 U73.4(ACKn)
N27843210: R1.1 U73.3(ENn)
N27851964: R302.1 U72.3(ENn)
N27851970: R307.1 U72.4(ACKn)
N30225833: P14.10(INSERT_COM) R304.1
N32582765: TP2.1 U73.1(VBUS_OUT.1) U73.2(VBUS_OUT.2)
N32636865: R325.1 SW1.3(A3)
N32636901: R323.1 SW1.4(A4)
N32675681: C86.1 L12.2 R179.1 U43.6(OUT3) U43.7(OUT2) U43.8(OUT1)

Not connected (* = marked no-connect by the designer): J1 4(ID)*; P10 5(MH1) 6(MH2); P11 5(MH1) 6(MH2); P12 4(TIPB) 5(MH1) 6(MH2); P13 4(TIPB) 5(MH1) 6(MH2); P14 11 12 13 14 15; RN12 4(R4A); RU5 9(3A) 12(4A); RU19 6(2B2); RU30 29(12B2) 30(12B1) 31(11B2) 32(11B1) 34(10B1) 36(9B1) 39(8B1) 41(7B1) 43(6B1) 45(5B1) 47(4B1) 50(3B1) 52(2B1) 54(1B1); RU93 7(3B3) 10(4B3) 12(5B3) 14(6B3) 16(7B3) 20(8B3) 22(9B3) 24(10B3) 26(11B3) 28(12B3); RU96 29(12B2) 30(12B1) 31(11B2) 32(11B1) 33(10B2) 34(10B1) 35(9B2) 36(9B1) 37(8B2) 42(6B2) 44(5B2) 46(4B2) 51(2B2); RU115 3(1B4)* 13(2B4)*; U2 3(RIn)* 5(NC.5)* 6(DSRn)* 7(DCDn)* 8(CTS#) 9(CBUS4)* 10(CBUS2)* 12(NC.12)* 13(NC.13)* 16(3V3OUT)* 18(RESET#)* 21(CBUS1)* 22(CBUS0)* 23(NC.23)* 25(NC.25)* 27(OSCI)* 28(OSCO)* 29(NC.29)* 31(DTR#)* 32(RTS#); U6 1(NC-1)* 2(NC-2)* 3(NC-3)* 4(NC-4)* 5(NC-5)* 6(NC-6)* 10(NC-7)* 11(NC-8)* 14(NC-9)* 15(NC-10)* 20(NC-11)* 21(NC-12)* 22(NC-13)* 23(NC-14)* 24(NC-15)* 35(22-NC)* 38(23-NC)*; U14 A1(NC.A1) A2(NC.A2) A6(NC.A6) A7(NC.A7) A8(NC.A8) A9(NC.A9) A10(NC.A10) A11(NC.A11) A12(NC.A12) A13(NC.A13) A14(NC.A14) B1(NC.B1) B7(NC.B7) B8(NC.B8) B9(NC.B9) B10(NC.B10) B11(NC.B11) B12(NC.B12) B13(NC.B13) B14(NC.B14) C1(NC.C1) C3(NC.C3) C5(NC.C5) C7(NC.C7) C8(NC.C8) C9(NC.C9) C10(NC.C10) C11(NC.C11) C12(NC.C12) C13(NC.C13) C14(NC.C14) D1(NC.D1) D2(NC.D2) D3(NC.D3) D4(NC.D4) D12(NC.D12) D13(NC.D13) D14(NC.D14) E1(NC.E1) E2(NC.E2) E3(NC.E3) E5(NC.E5) E8(NC.E8) E9(NC.E9) E10(NC.E10) E12(NC.E12) E13(NC.E13) E14(NC.E14) F1(NC.F1) F2(NC.F2) F3(NC.F3) F10(NC.F10) F12(NC.F12) F13(NC.F13) F14(NC.F14) G1(NC.G1) G2(NC.G2) G3(NC.G3) G10(NC.G10) G12(NC.G12) G13(NC.G13) G14(NC.G14) H1(NC.H1) H2(NC.H2) H3(NC.H3) H5(NC.H5) H12(NC.H12) H13(NC.H13) H14(NC.H14) J1(NC.J1) J2(NC.J2) J3(NC.J3) J5(NC.J5) J12(NC.J12) J13(NC.J13) J14(NC.J14) K1(NC.K1) K2(NC.K2) K3(NC.K3) K6(NC.K6) K7(NC.K7) K10(NC.K10) K12(NC.K12) K13(NC.K13) K14(NC.K14) L1(NC.L1) L2(NC.L2) L3(NC.L3) L12(NC.L12) L13(NC.L13) L14(NC.L14) M1(NC.M1) M2(NC.M2) M3(NC.M3) M7(NC.M7) M8(NC.M8) M9(NC.M9) M10(NC.M10) M11(NC.M11) M12(NC.M12) M13(NC.M13) M14(NC.M14) MA4(NC.MA4) MA6(NC.MA6) MA9(NC.MA9) MA11(NC.MA11) MAE1(NC.MAE1) MAE14(NC.MAE14) MAG2(NC.MAG2) MAG13(NC.MAG13) MAH4(NC.MAH4) MAH6(NC.MAH6) MAH9(NC.MAH9) MAH11(NC.MAH11) MB2(NC.MB2) MB13(NC.MB13) MD1(NC.MD1) MD14(NC.MD14) N1(NC.N1) N3(NC.N3) N6(NC.N6) N7(NC.N7) N8(NC.N8) N9(NC.N9) N10(NC.N10) N11(NC.N11) N12(NC.N12) N13(NC.N13) N14(NC.N14) P1(NC.P1) P2(NC.P2) P7(NC.P7) P8(NC.P8) P9(NC.P9) P10(NC.P10) P11(NC.P11) P12(NC.P12) P13(NC.P13) P14(NC.P14); U18 4(DNU.4) 5(DNU.5) 6(RFU.6) 11(DNU.11) 12(DNU.12) 13(NC.13); U25 1(NC1); U26 1(NC1); U55 4(NC/FB)*; U59 4(LINE1L-) 6(LINE1R-) 7(LINE2L+) 8(LINE2L-) 9(LINE2R+) 10(LINE2R-) 12(MICDET) 19(HPLCOM) 22(HPRCOM) 27(MONO_LO+) 28(MONO_LO-) 30(LEFT_LO-) 32(RIGHT_LO-) 34(GPIO2) 35(GPIO1); U77 2(NC.2); U78 2(NC.2); U79 2(NC.2); U83 27(NC1)* 28(NC2)* 30(NC3)*; U122 2(NC.2) 3(IO1); U1027 1(NC1); U1028 3(~{MR}); U1033 1(NC1); U1034 1(NC1)

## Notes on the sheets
sheet 23
- ER10
- INTERNAL TESTING.
sheet 24
- HHL  A1 TO B1, A2 TO B2: : DEFAULT
  LHH A2 TO B1 : NOR ALT ADDR
- THIS IS OUTPUT OF THE GPMC_A/MMC2
  MUX, I.E. 2 MUX DELAY.
sheet 25
- A = B1 LLH : ENET, xxx_S2=1,xxx_S0=1
  A = B2 LHL : VIN2, xxx_S2=1,xxx_S0=0
  A = B3 HLH : CAM , xxx_S2=0,xxx_S0=1
- vin2a_d[12]
  vin2a_d[13]
  vin2a_d[14]
  vin2a_d[15]
  vin2a_d[16]
  vin2a_d[17]
  vin2a_d[18]
  vin2a_d[19]
  vin2a_d[20]
  vin2a_d[21]
  vin2a_d[22]
  vin2a_d[23]
- rgmii1_txc
  rgmii1_txctl
  rgmii1_txd[3]
  rgmii1_txd[2]
  rgmii1_txd[1]
  rgmii1_txd[0]
  rgmii1_rxc
  rgmii1_rxctl
  rgmii1_rxd[3]
  rgmii1_rxd[2]
  rgmii1_rxd[1]
  rgmii1_rxd[0]
sheet 26
- ROUTE THE FOLLOWING SIGNALS AS A GROUP
  WITH A NET LENGTH LESS THEN 2.75
  INCHES AND 60ps OF SKEW.  PLACE THE
  DUAL RESISTOR CLOSE TOGETHER NEAR THE
  PIN OF THE FLASH.
- AQSPI1_SCLK
  AQSPI1_RTCLK
  AQSPI1_CS[0]
  AQSPI1_D[0]
  AQSPI1_D[1]
  AQSPI1_D[2]
  AQSPI1_D[3]
- R730/R132
sheet 29
- ER6
- DUAL FOOTPRINT 153/169 USES 153 PIN
  NUMBERS FOR COMPATIBLE PINS.
sheet 30
- ER7
- ~97 micro second ramp
sheet 32
- FILTERS
- USB2 / USB3: DLW21SN670HQ2 or DLW21SN121HQ2
- ESD
- USB2: TPD4S012DRY replace with TPD4S014 (TPD4S014-Q1)
- FILTERS
- USB2 / USB3: DLW21SN670HQ2 or DLW21SN121HQ2
- PCIE PADS SHARE PIN 1/4 WITH FL2/3.
  FLx NO-POP, PCIE SIGNALS CAN BE POP
  WITH 0201 OR SOLDER BRIDGE.
- ESD
- USB2: TPD4S012DRY replace with TPD4S014 (TPD4S014-Q1)
  USB3:  TPD4EUSB30 replace with two TPD2EUSB30 (TPD2EUSB30-Q1) in drt package
sheet 33
- REV D
sheet 34
- CENTER TO CENTER SPACING CAN BE
  0.425 INCHES FOR CABLES
